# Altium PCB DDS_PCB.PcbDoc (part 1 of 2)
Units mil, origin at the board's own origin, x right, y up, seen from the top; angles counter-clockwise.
Board outline 3998.07 x 3476.44 mil, 8 copper layers (TOP_L1, Plane_L2, Inner_L3, Plane_L4, Plane_L5, Inner_L6, Plane_L7, Bottom Layer_L8), stack 26.8 mil thick; 448 components, 266 nets, 1489 pads, 18 vias.
Unrouted connection lines stored in the file: 995.
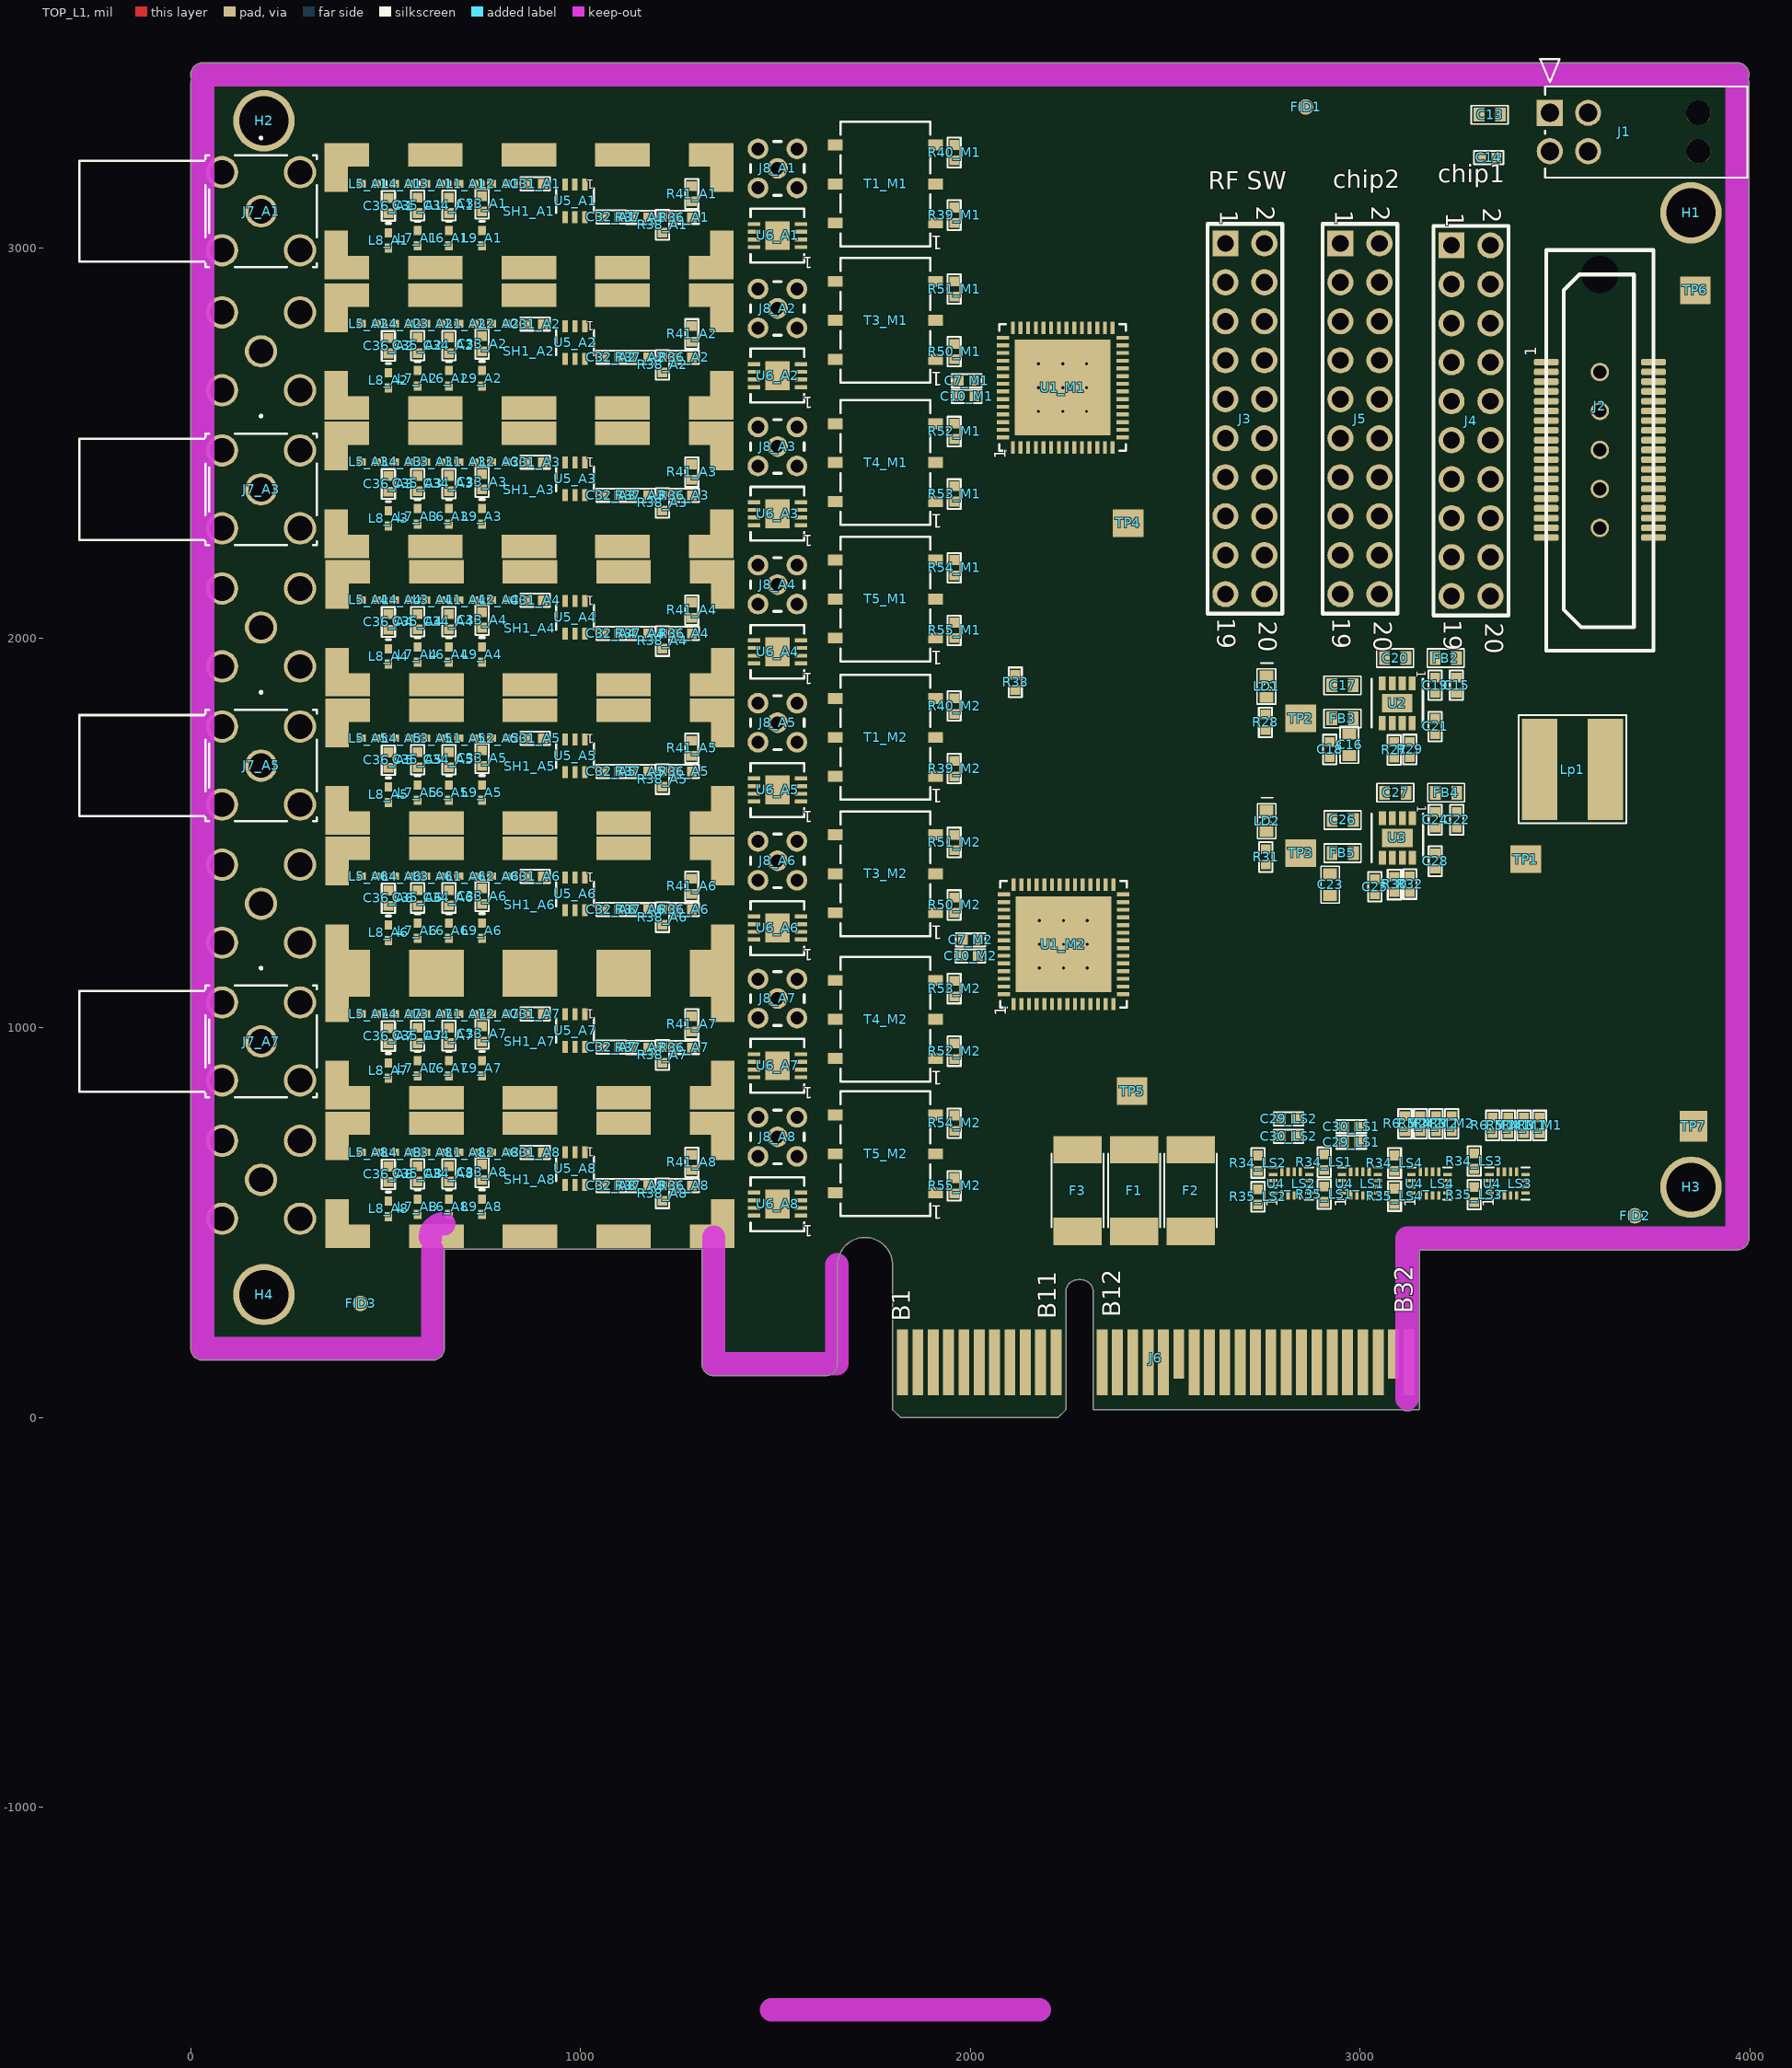
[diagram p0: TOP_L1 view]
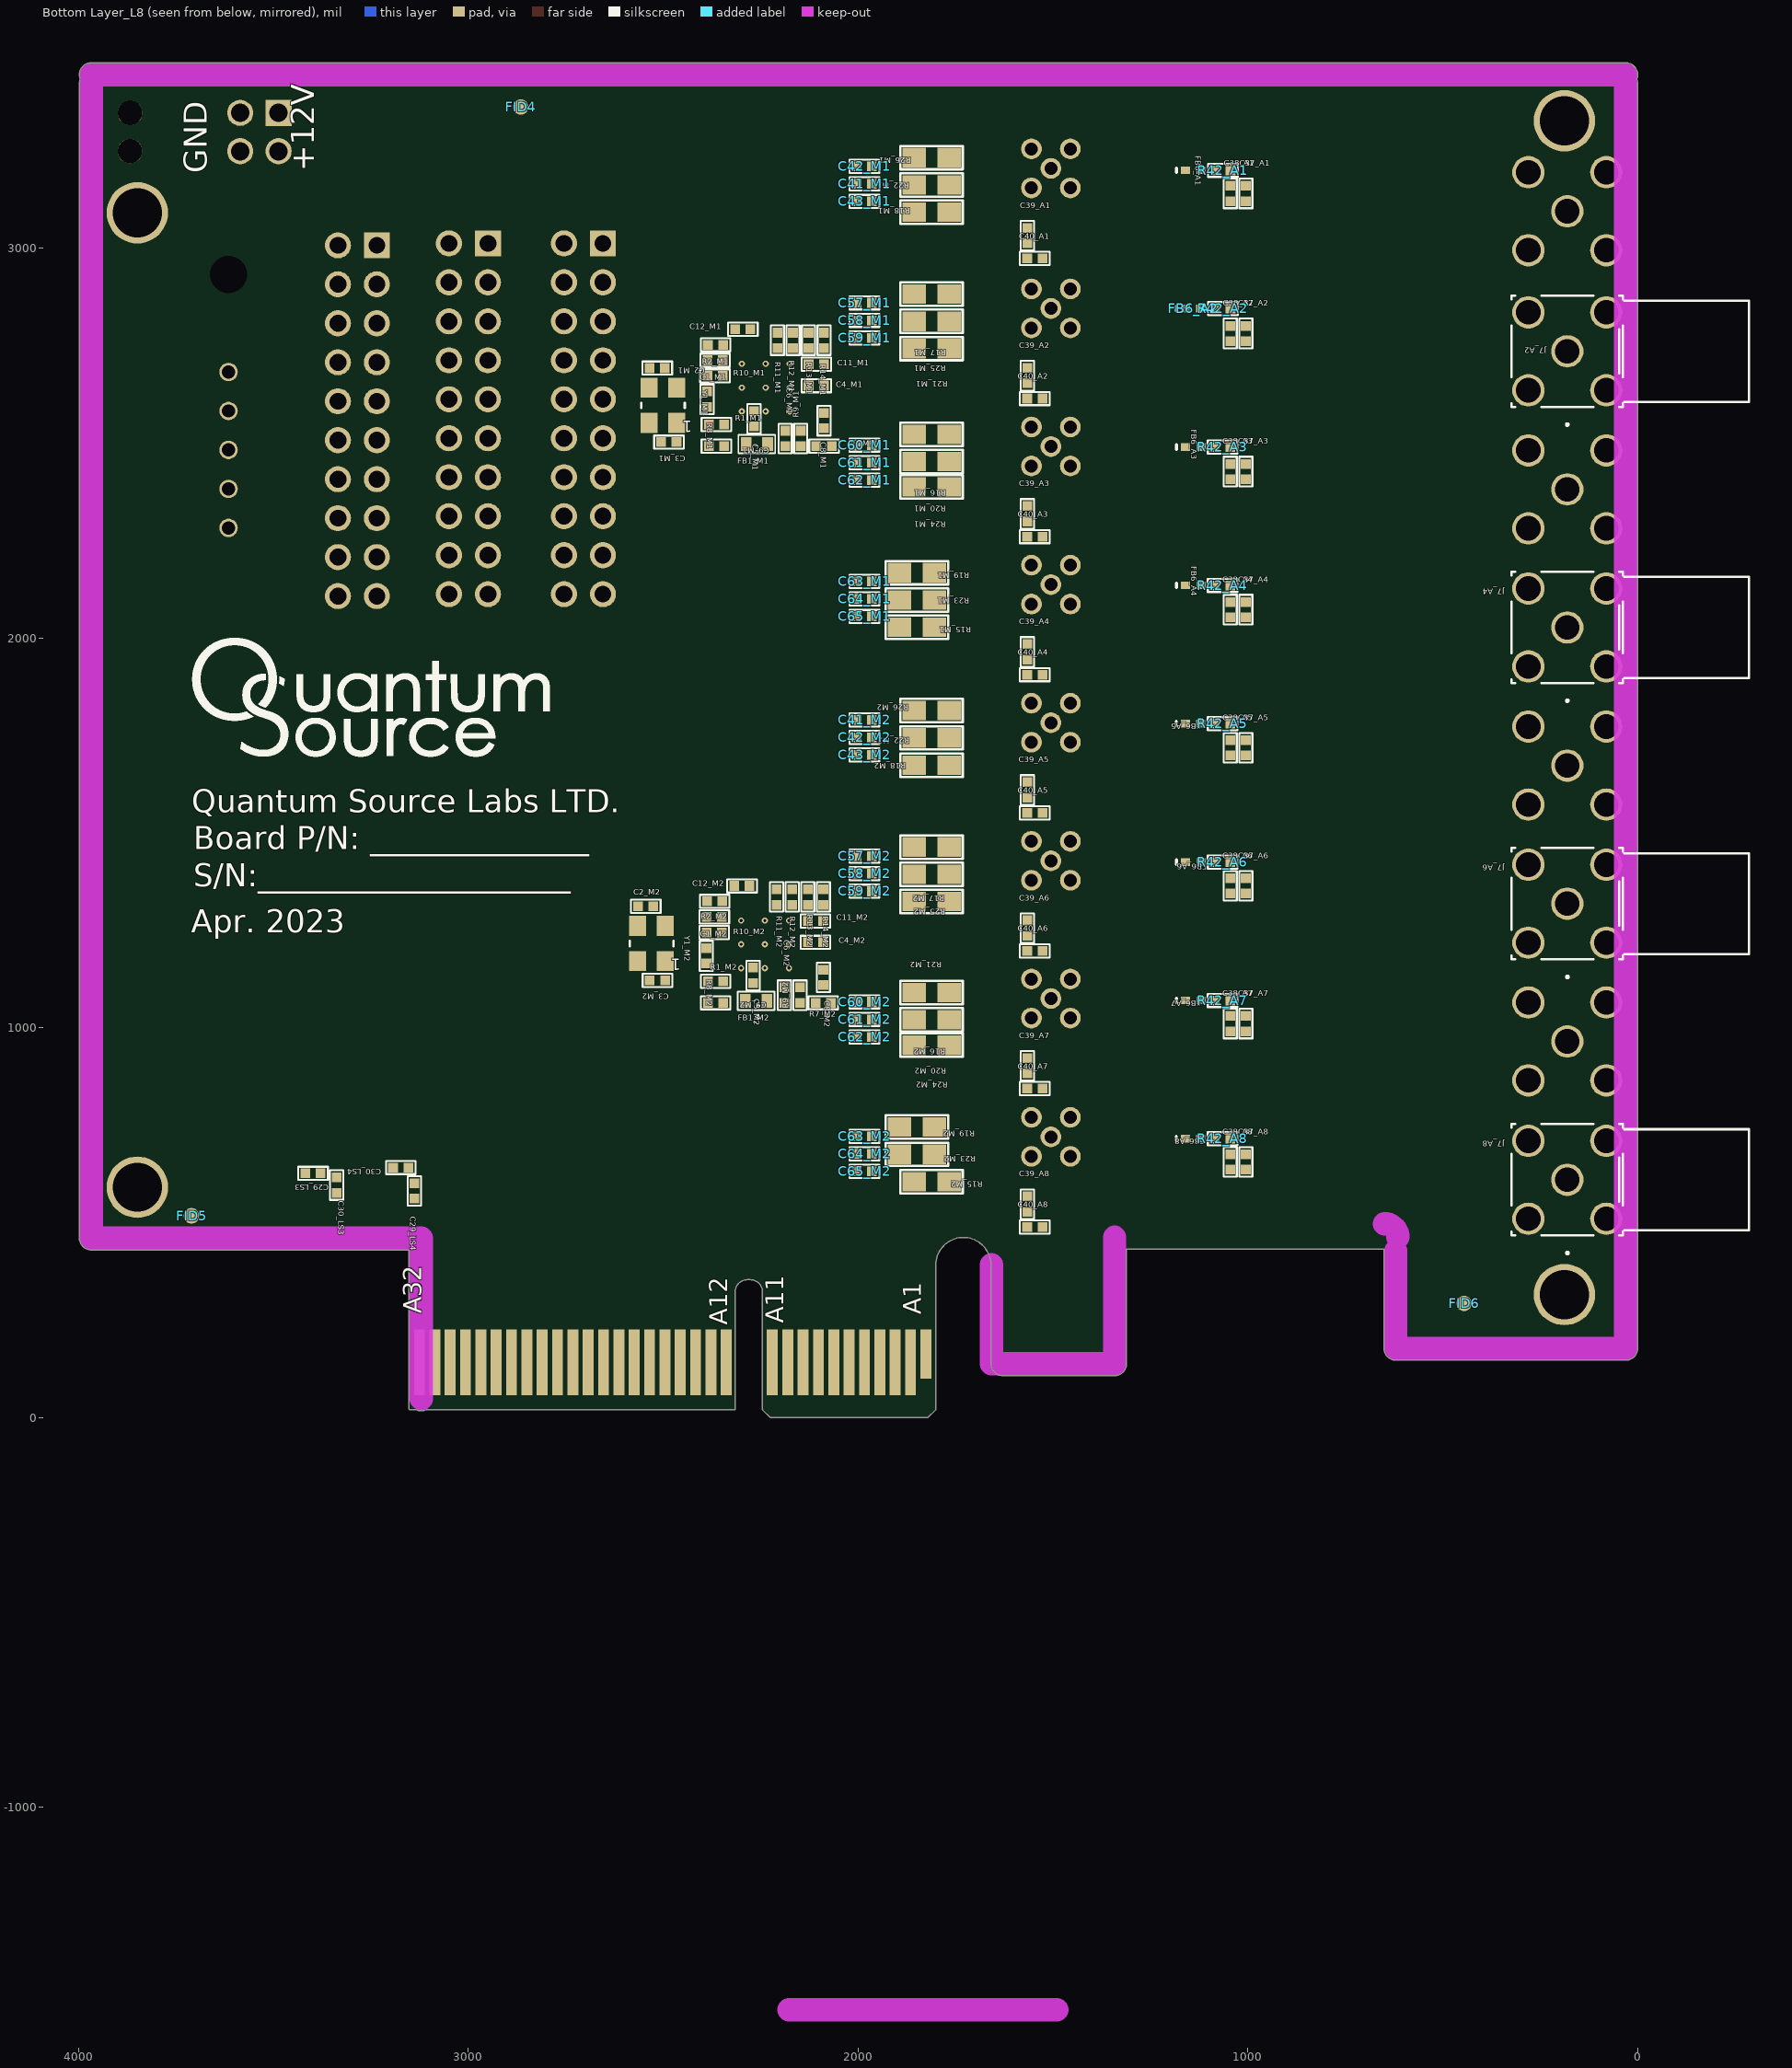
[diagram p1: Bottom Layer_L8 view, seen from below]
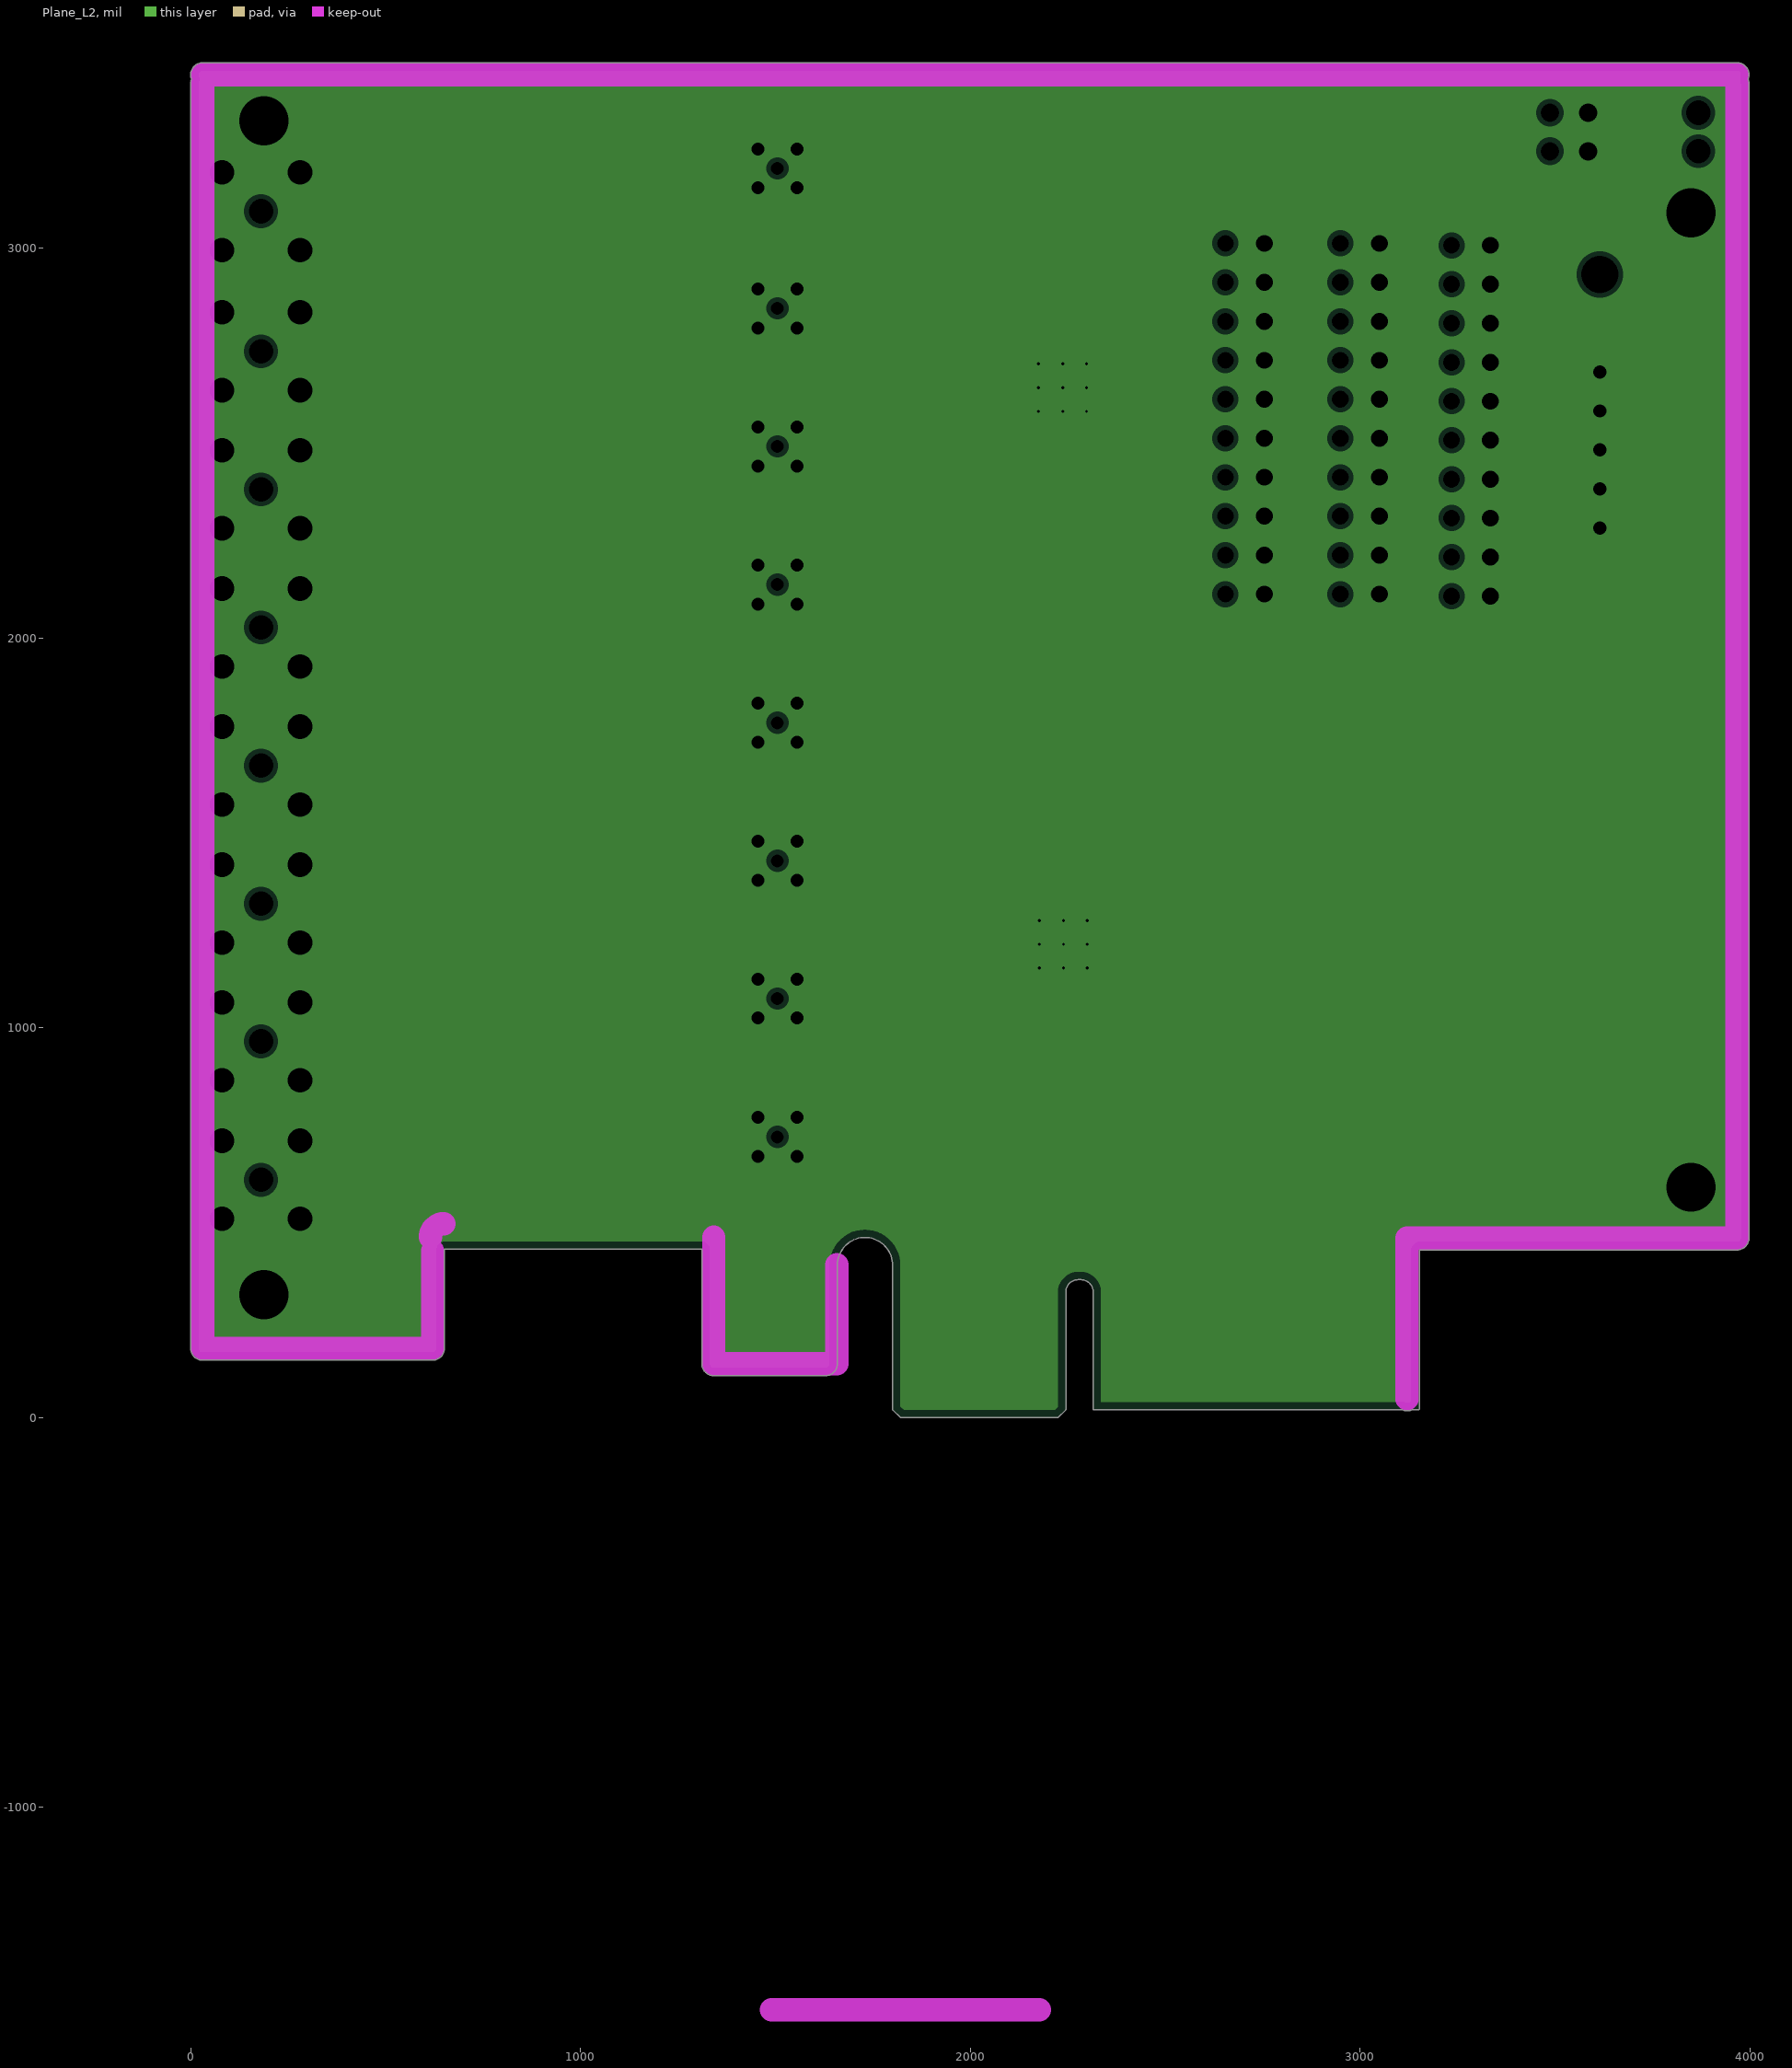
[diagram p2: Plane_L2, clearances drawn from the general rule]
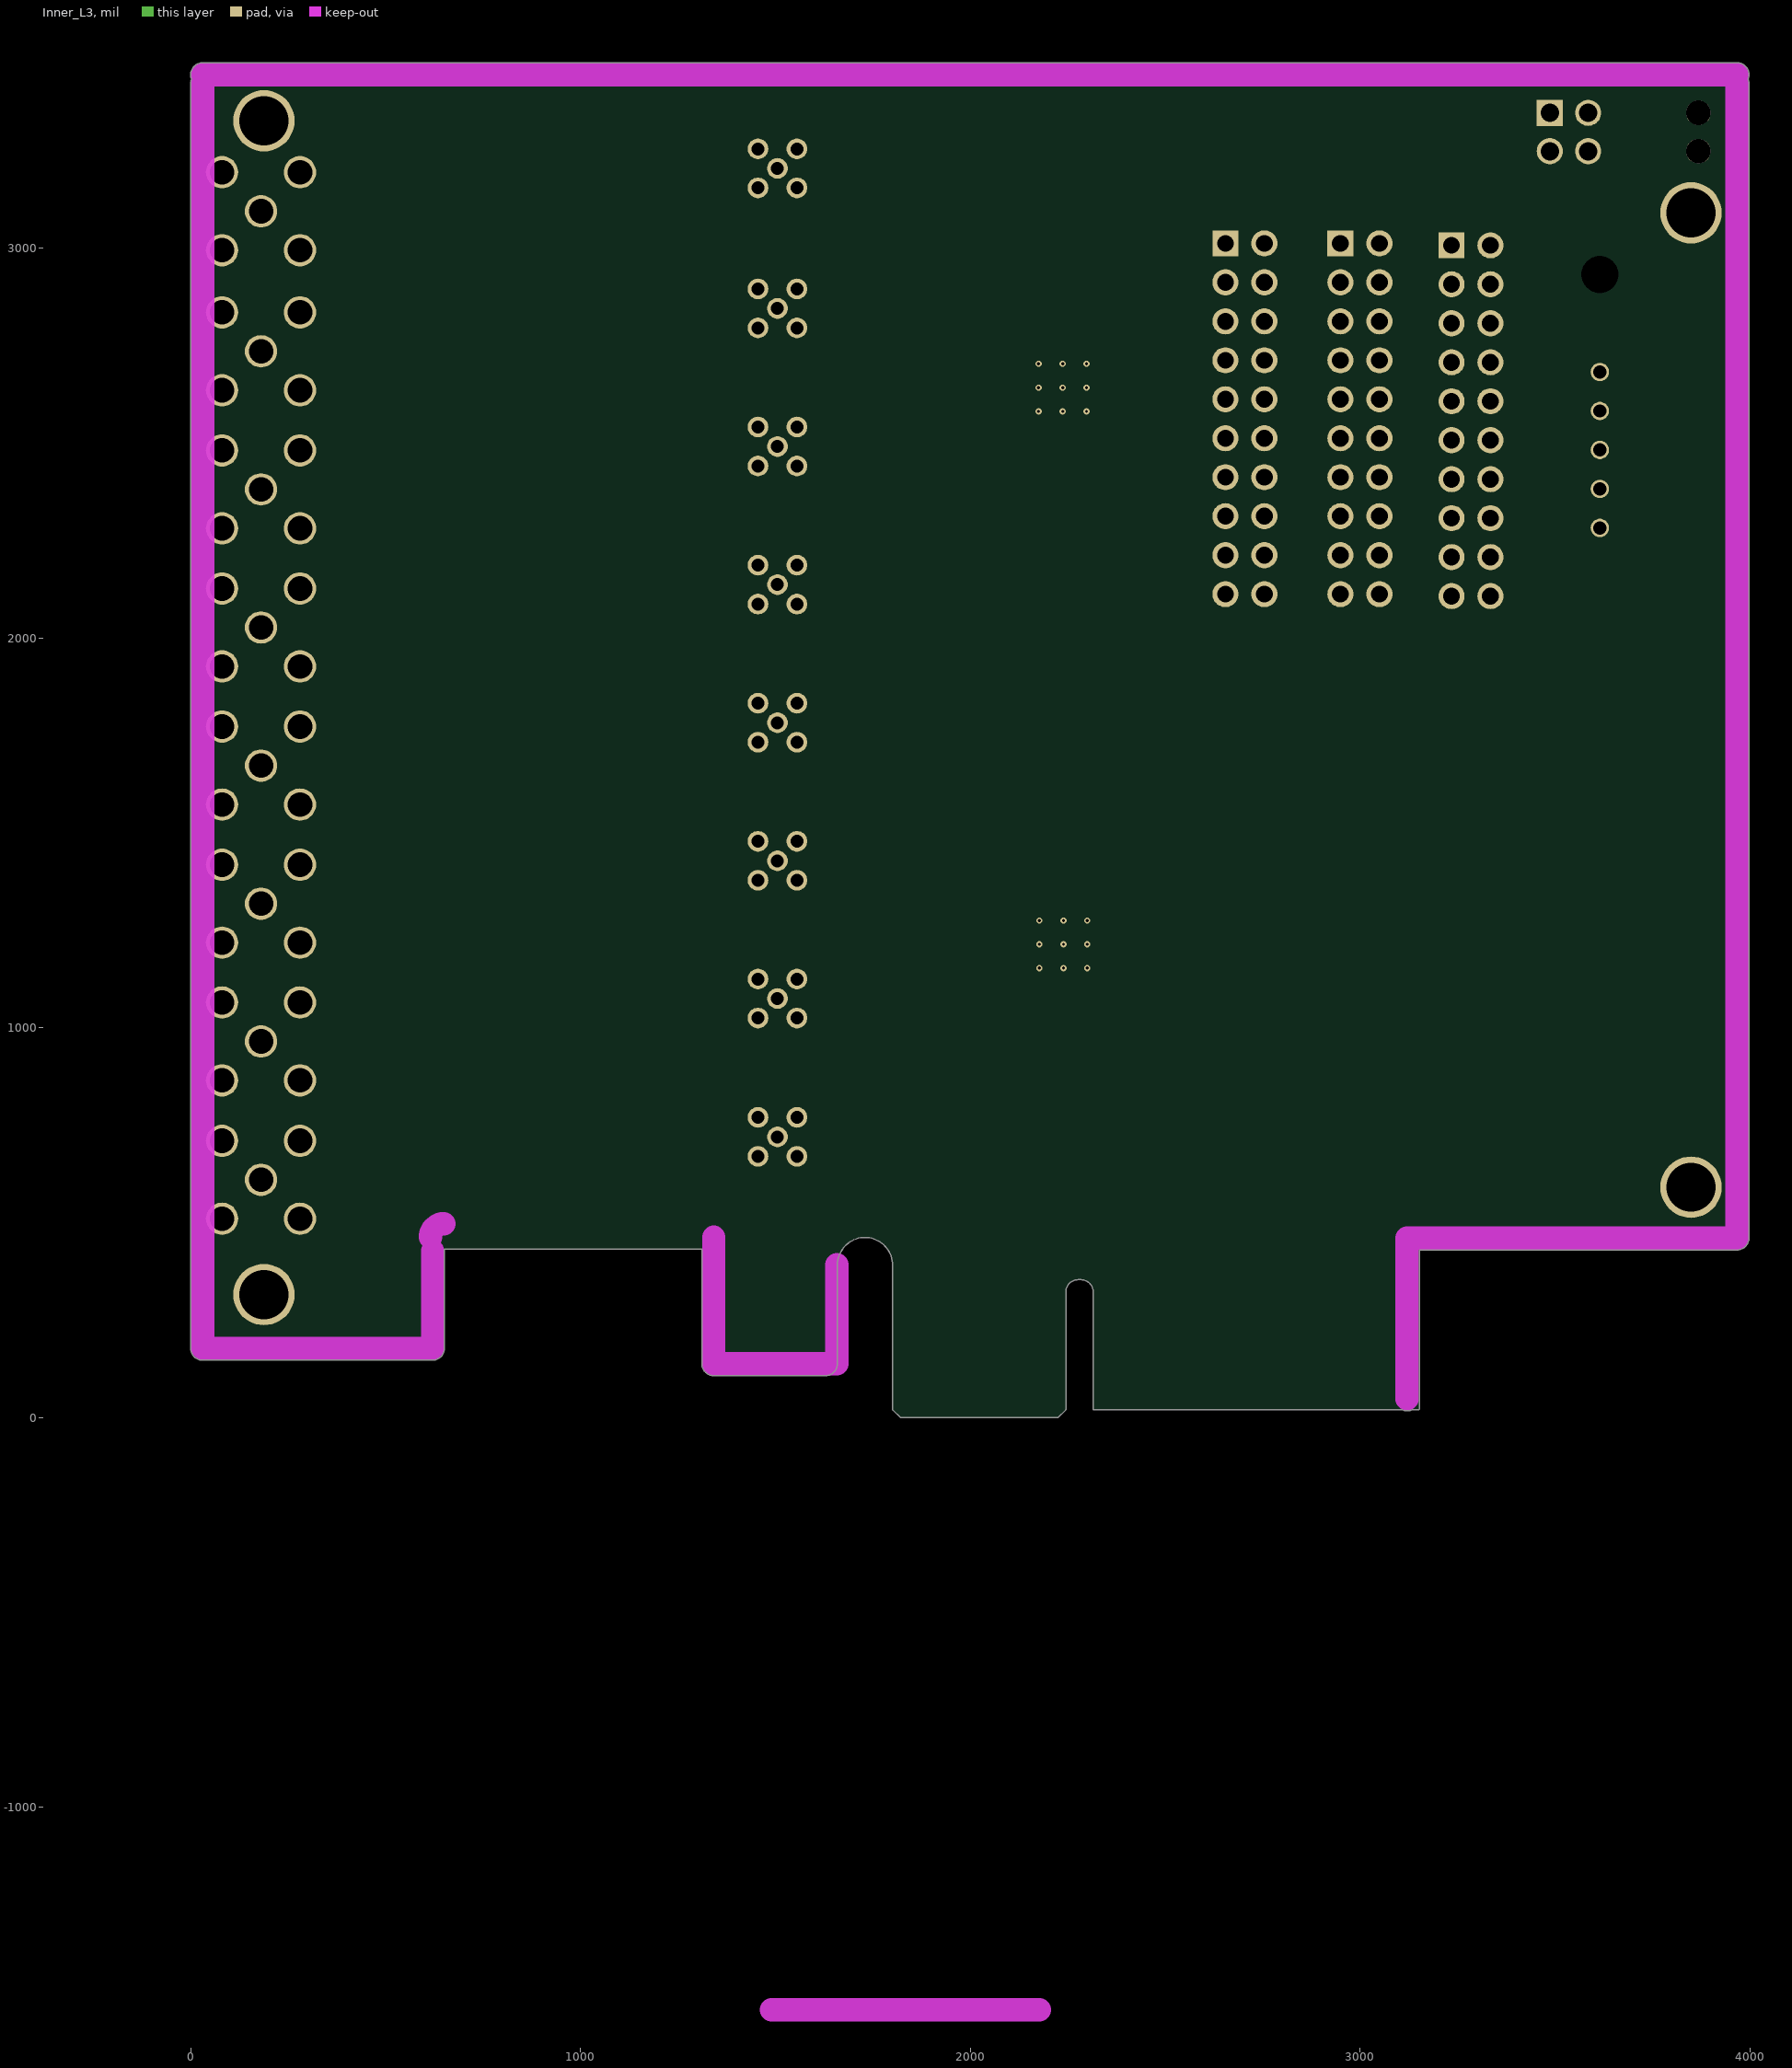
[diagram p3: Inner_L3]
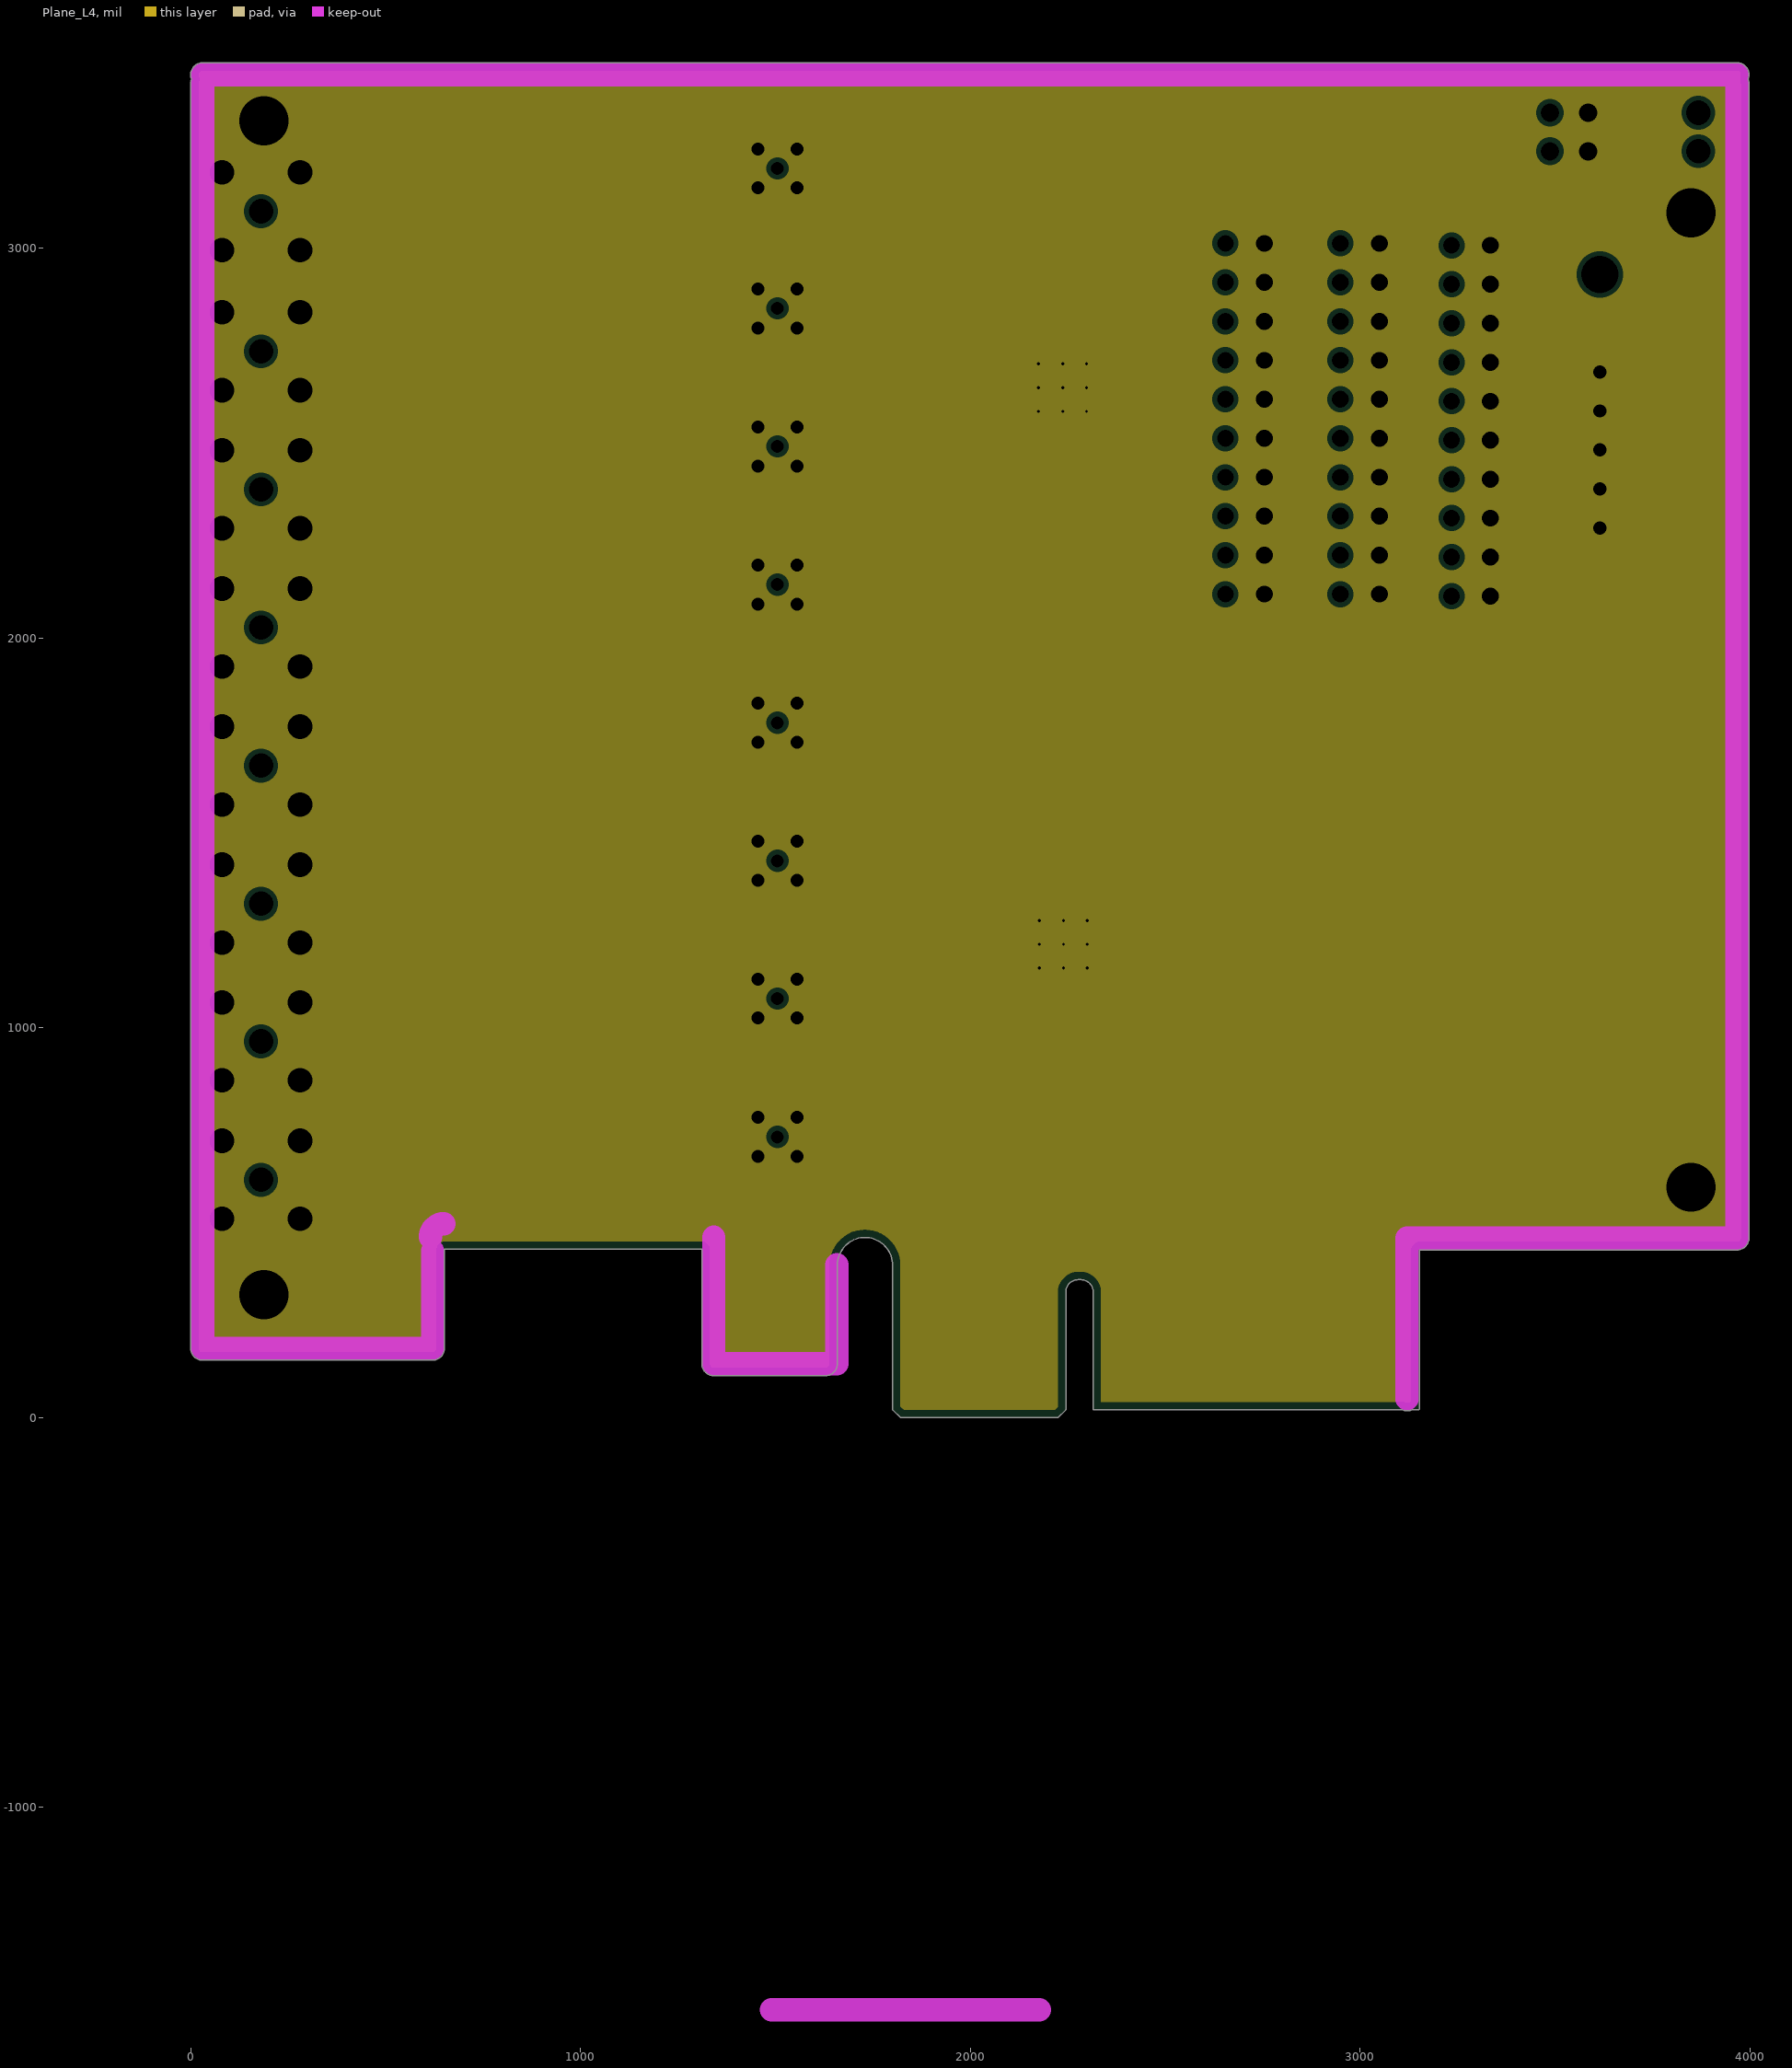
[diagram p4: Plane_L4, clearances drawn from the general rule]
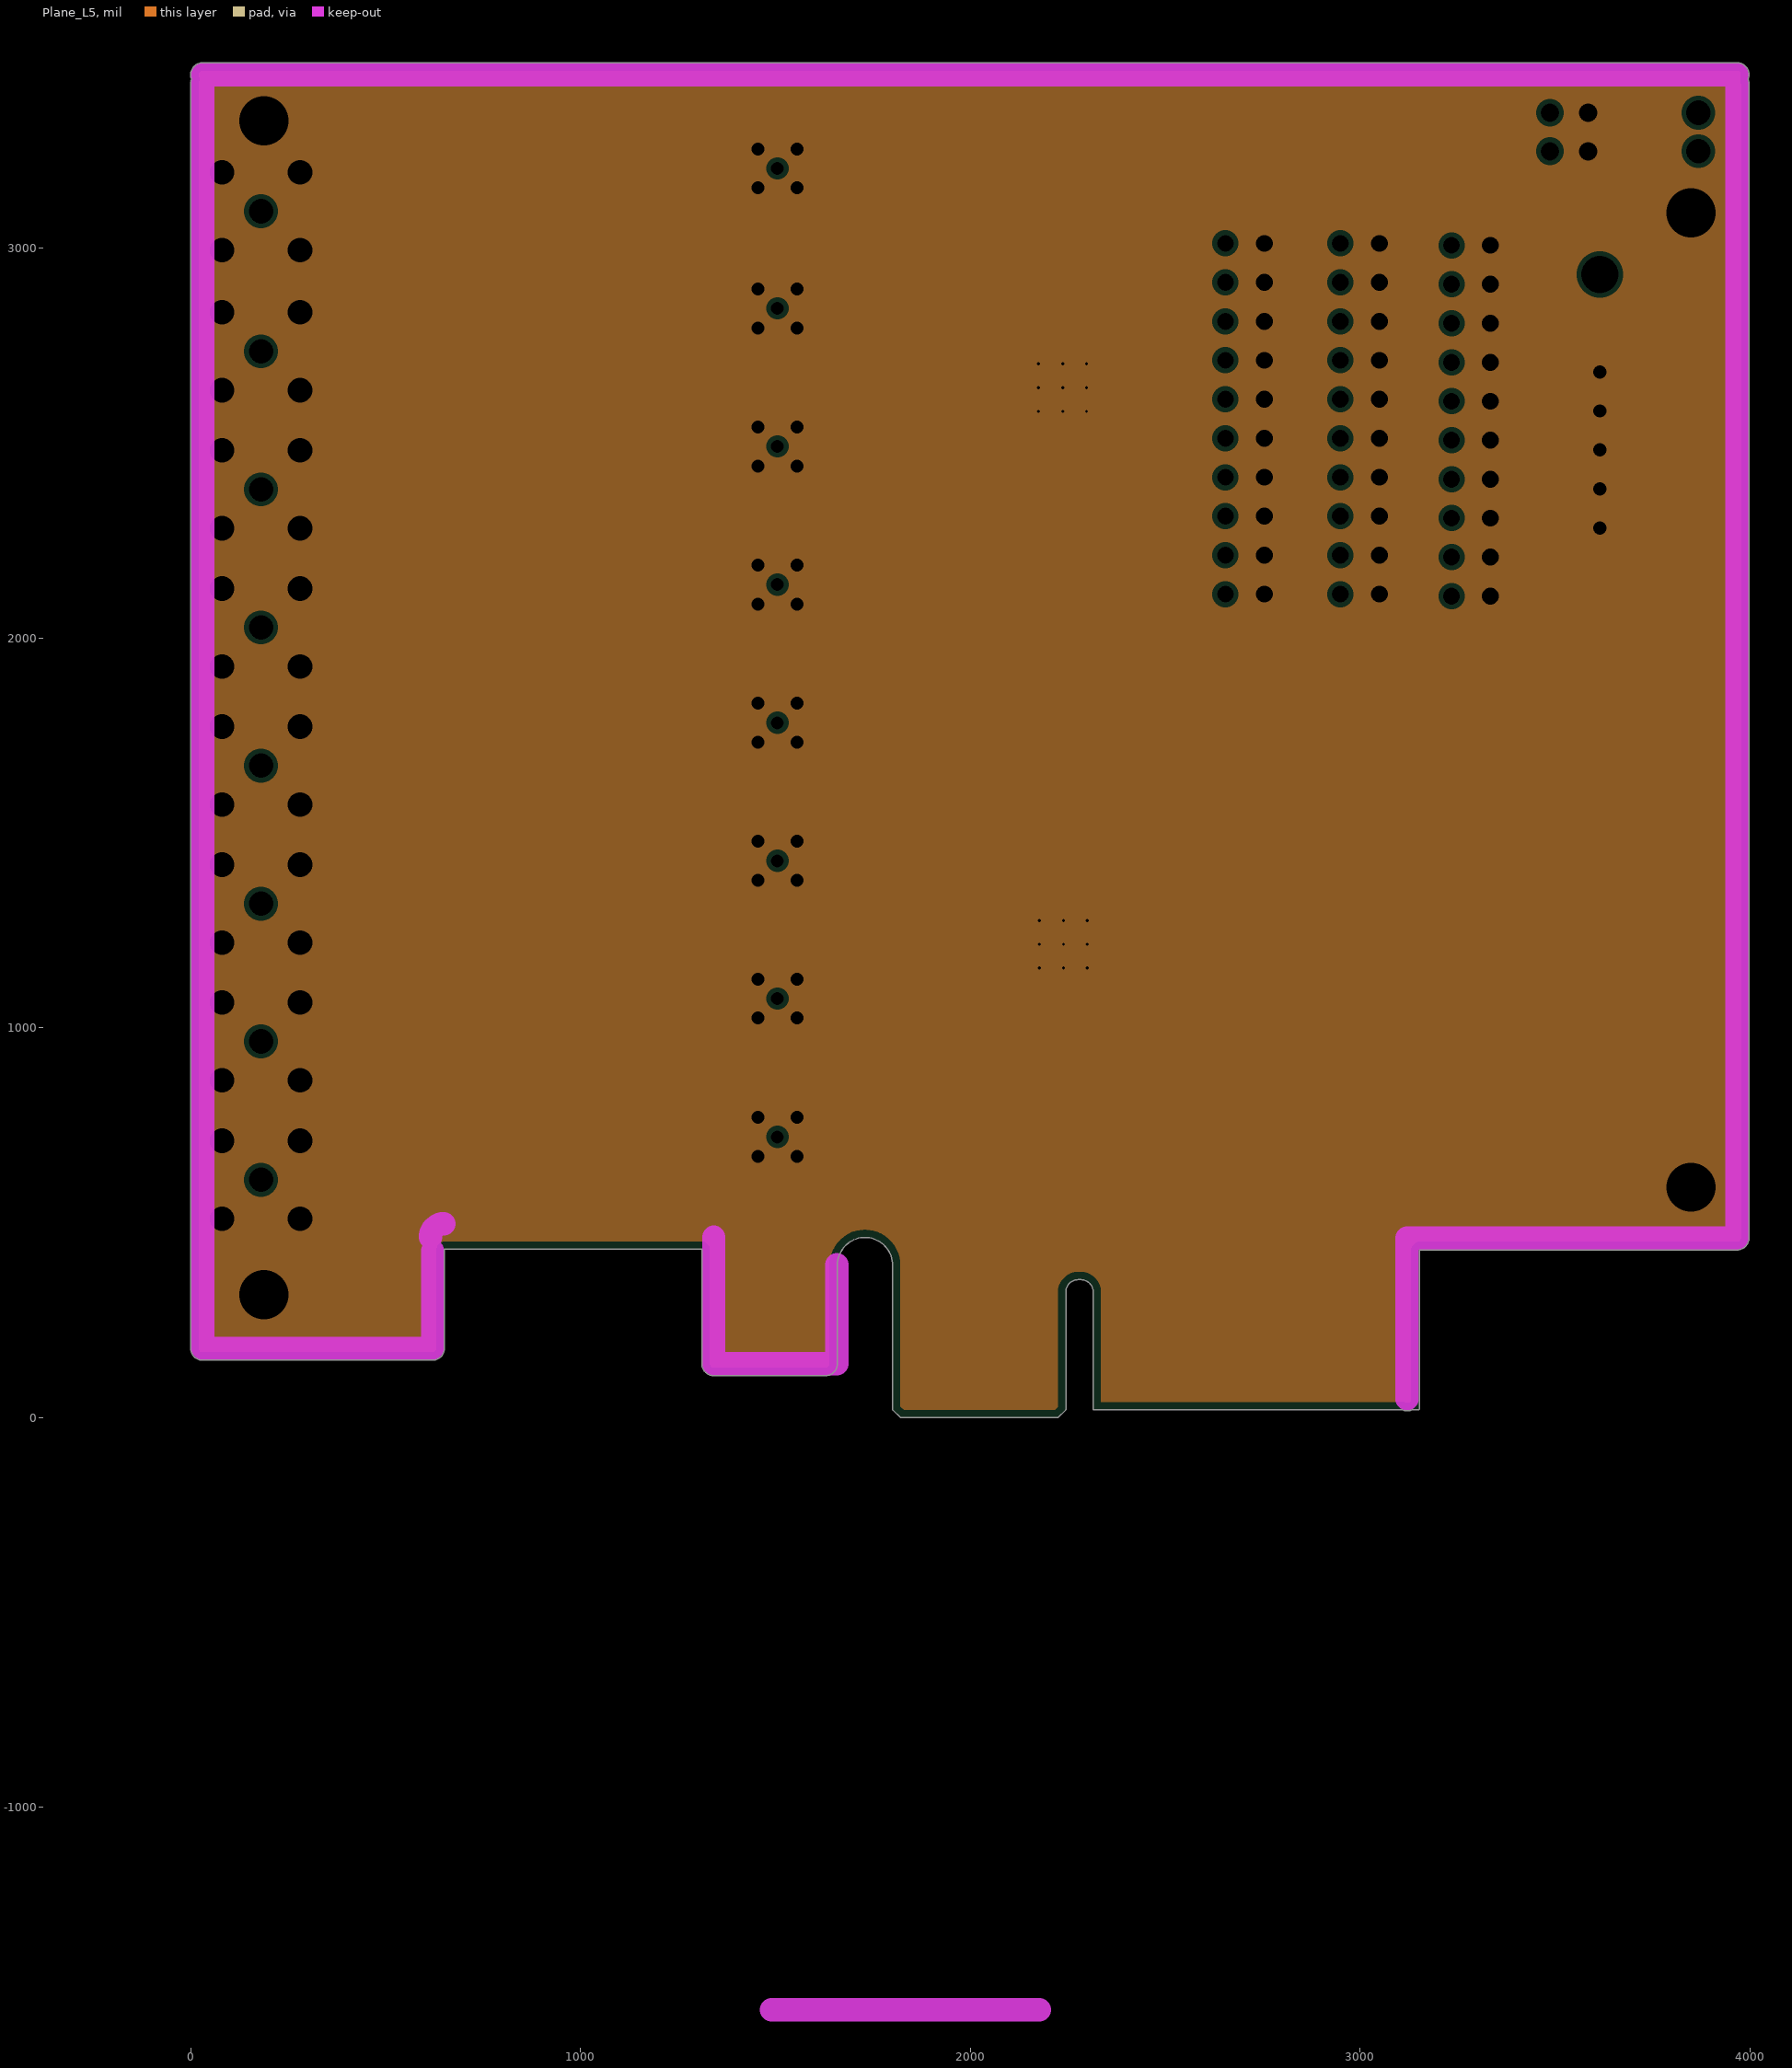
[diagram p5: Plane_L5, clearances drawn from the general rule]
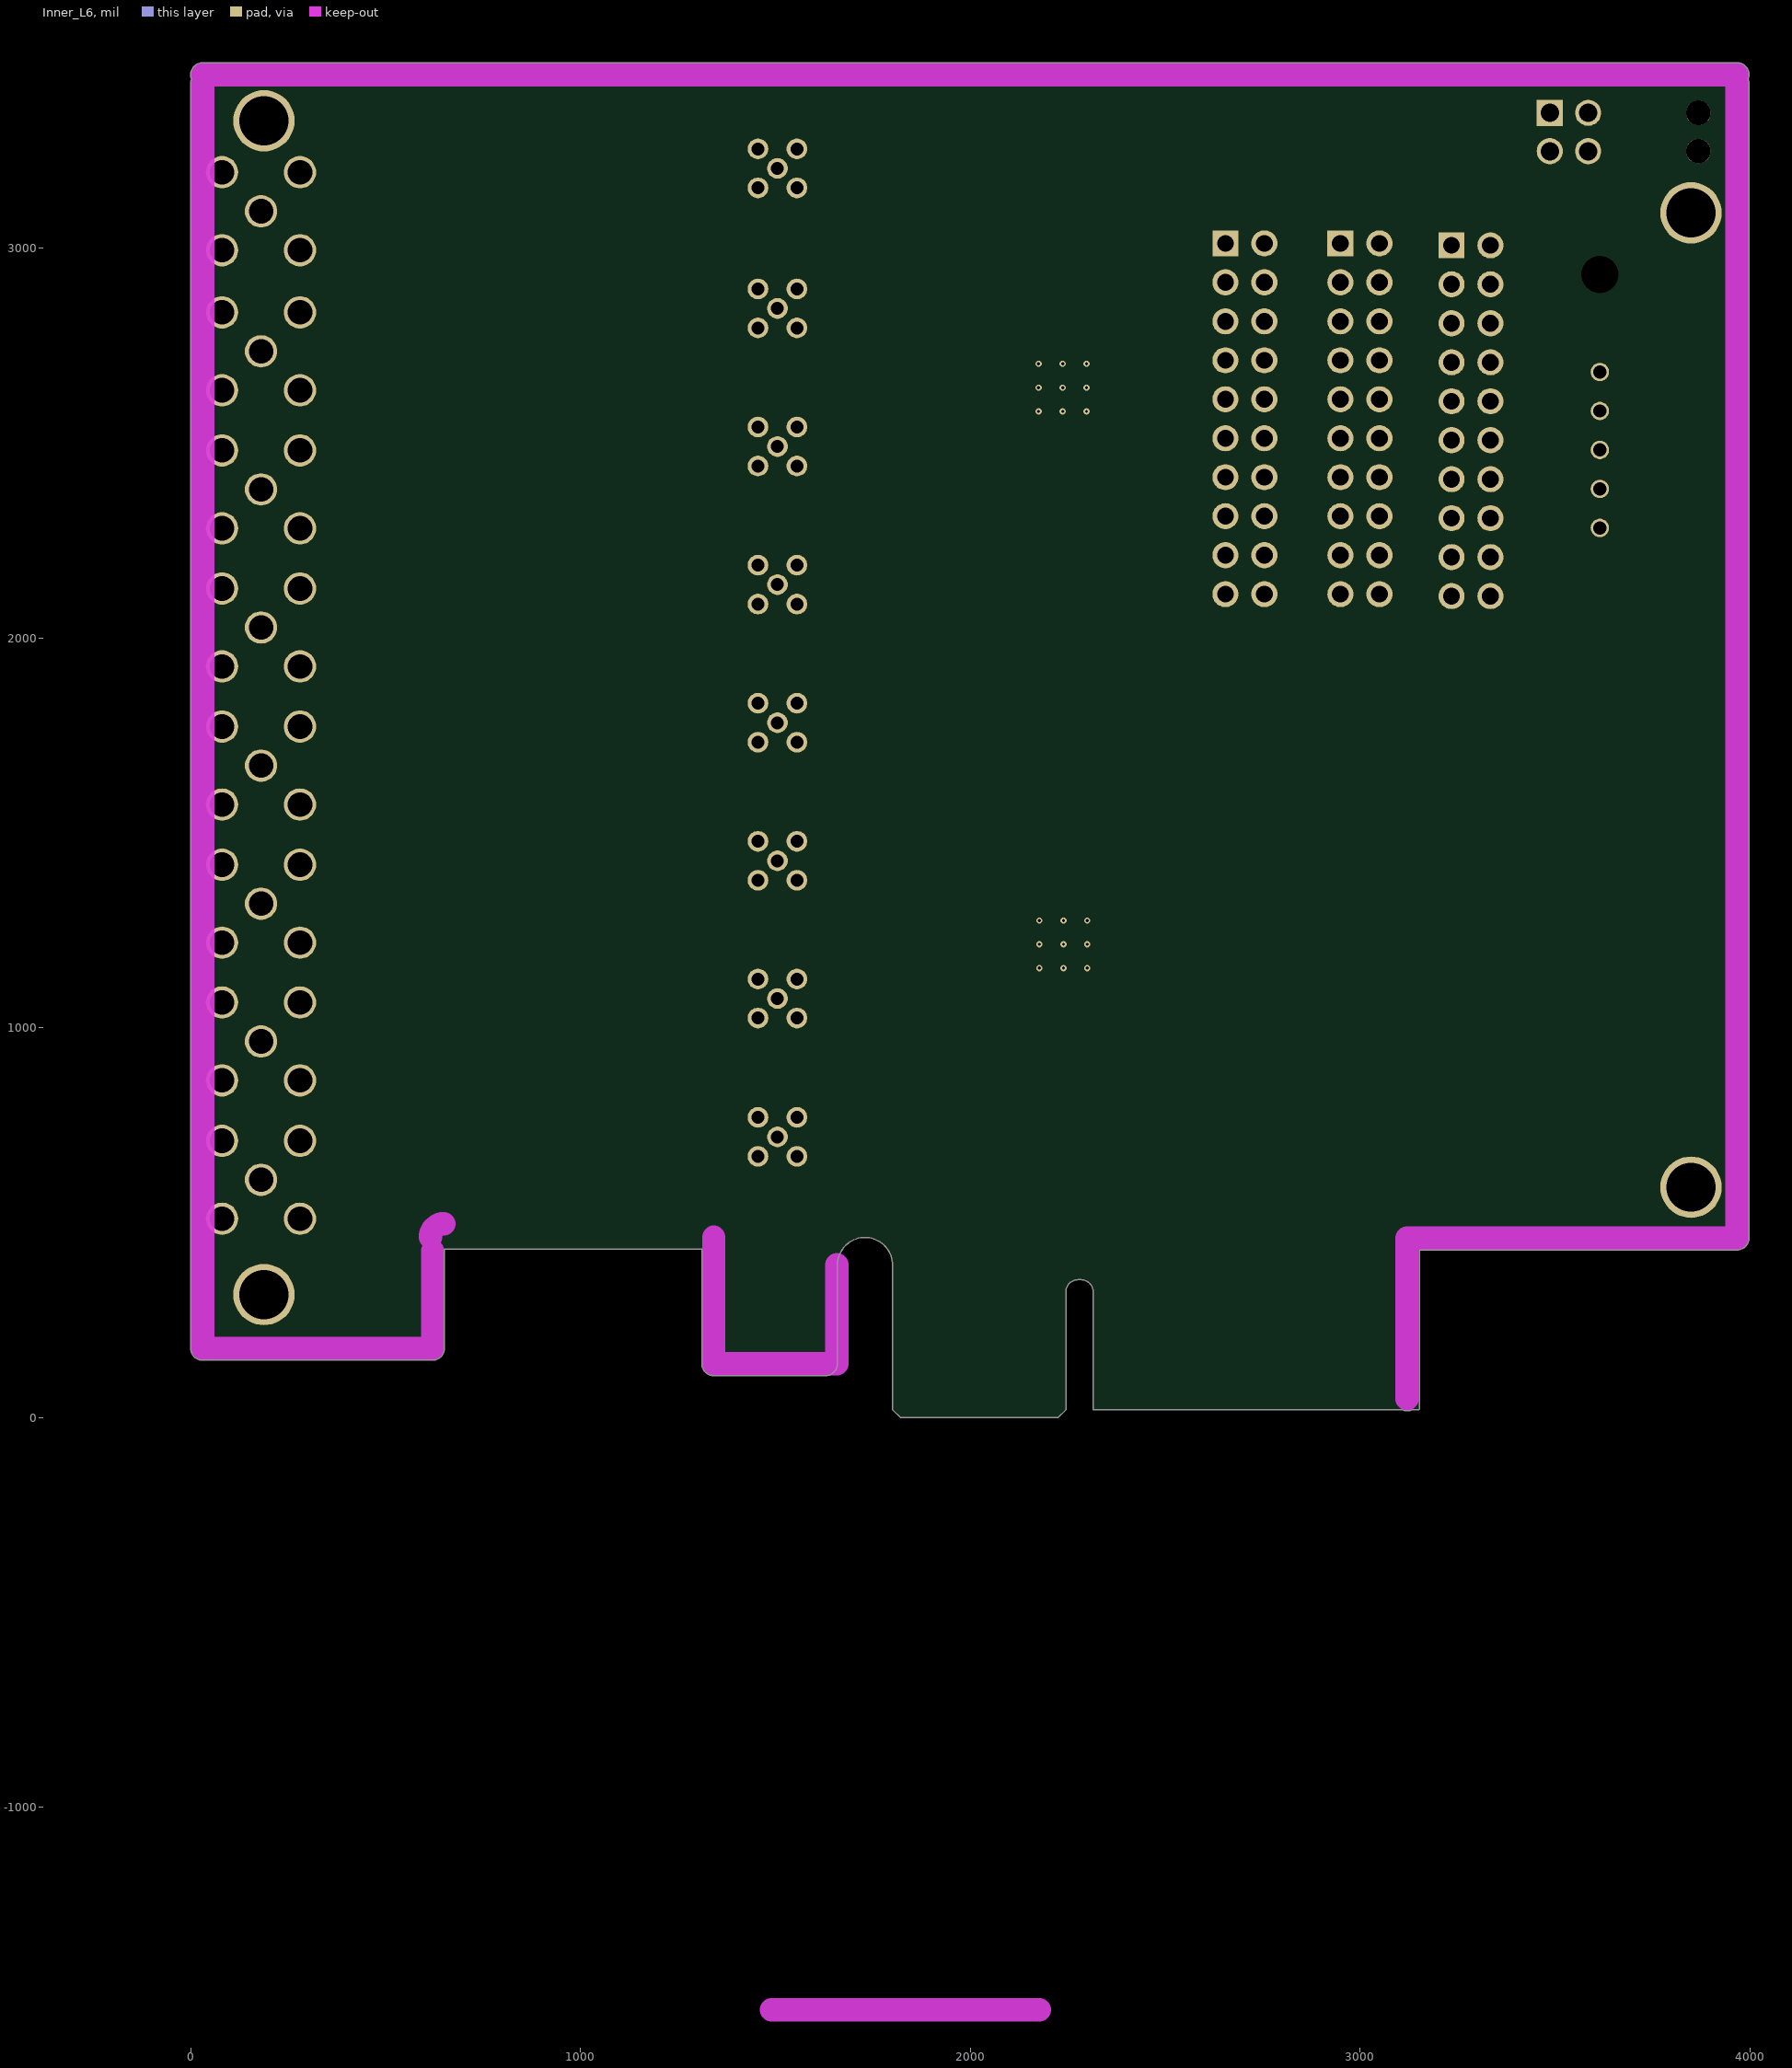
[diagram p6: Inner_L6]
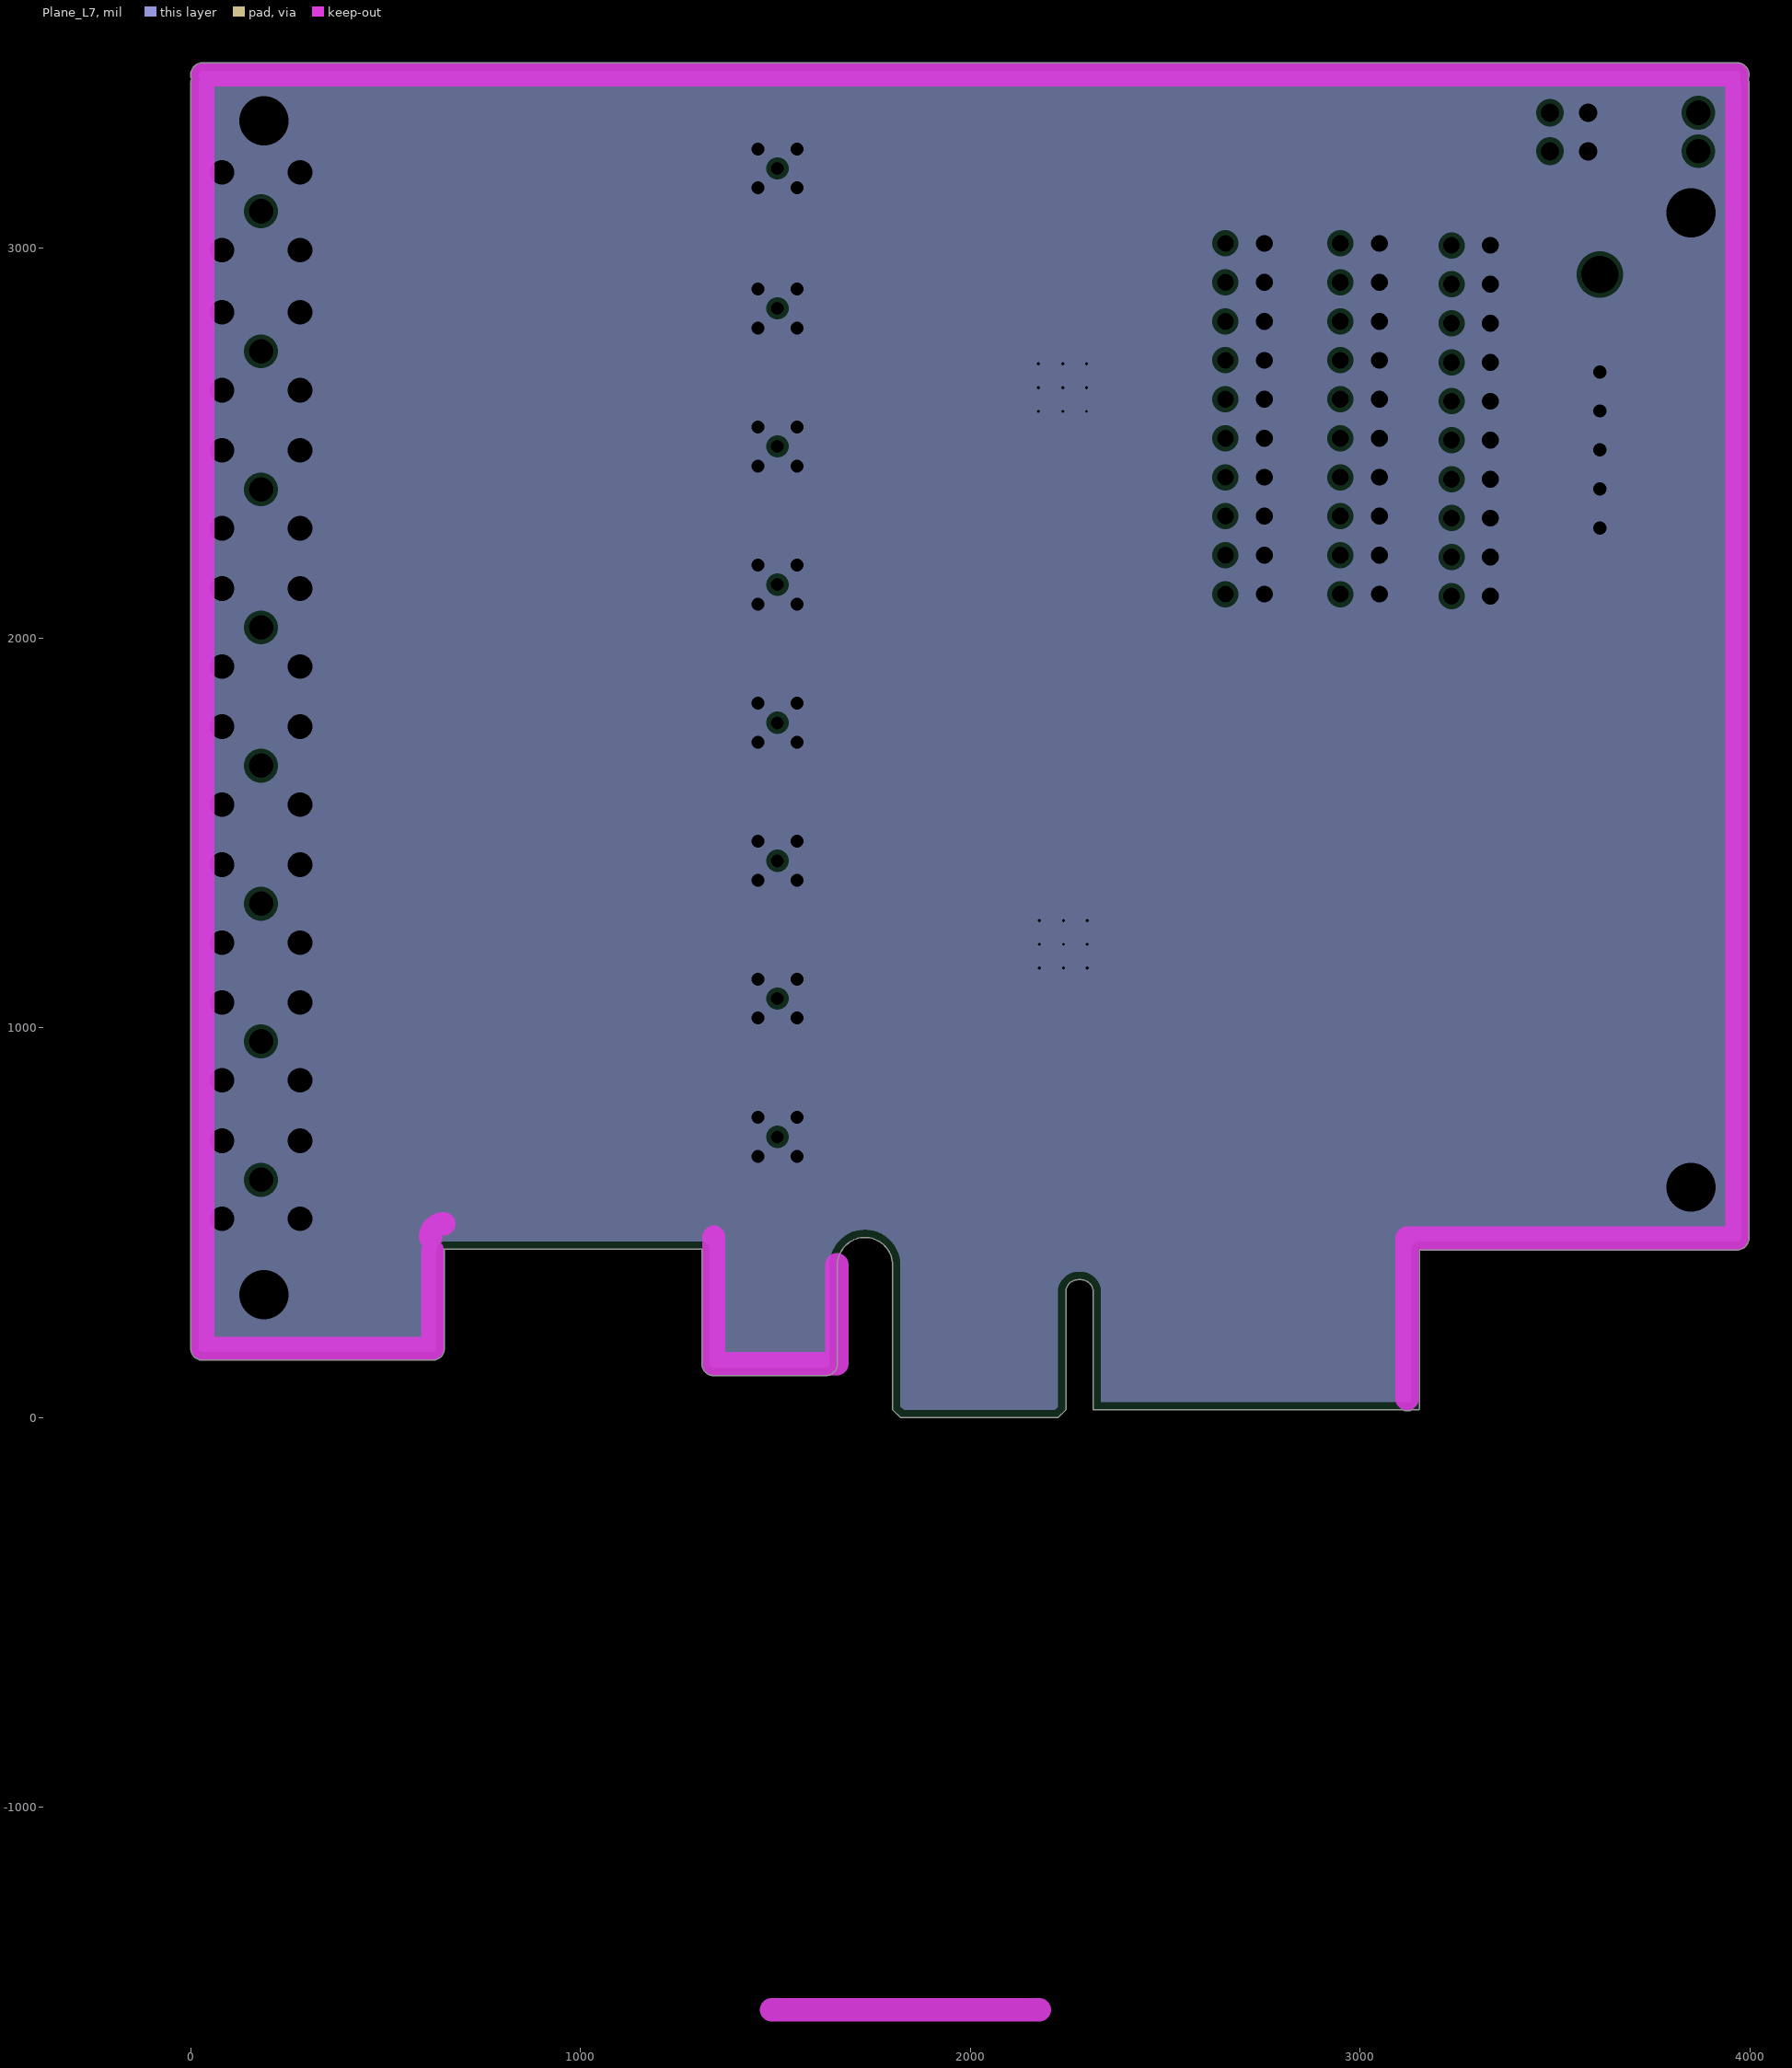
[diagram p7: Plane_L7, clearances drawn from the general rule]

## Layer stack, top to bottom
Top Solder: solder mask 0.4, Solder Resist, Dk 3.5
TOP_L1: signal copper 0.6
Dielectric1: core 2.9, FR-4, Dk 3.2
Plane_L2: plane copper 0.7, net GND
Dielectric7: prepreg 3, FR-4, Dk 3.3
Inner_L3: signal copper 0.7
Dielectric4: core 2.8, FR-4, Dk 3.1
Plane_L4: plane copper 1.2, net GND
Dielectric10: prepreg 3, FR-4, Dk 3.3
Plane_L5: plane copper 1.2, net GND
Dielectric 1: core 2.8, FR-4, Dk 3.1
Inner_L6: signal copper 0.7
Dielectric 6: prepreg 3, FR-4, Dk 3.3
Plane_L7: plane copper 0.7, net GND
Dielectric 7: core 2.9, FR-4, Dk 3.2
Bottom Layer_L8: signal copper 0.6
Board Layer Stack Bottom Solder: solder mask 0.4, Solder Resist, Dk 3.5

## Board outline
30.02,147 cw(c30.02,177.53) -0.51,177.53 -0.51,3422.53 cw(c30.02,3422.53) 1.68,3433.89 cw(c30.02,3445.25) 30.01,3475.78 30.02,3475.78 3967.02,3475.78 cw(c3967.02,3445.25) 3997.55,3445.25 3997.55,3445.24 cw(c3967.02,3445.25) 3995.36,3433.89 cw(c3967.02,3422.53) 3997.55,3422.54 3997.55,3422.53 3997.55,460.41 cw(c3967.02,460.4) 3967.02,429.87 3151.68,429.87 3151.68,20.57 3150.65,19.54 3132.64,19.54 cw(c3120.65,47.61) 3108.65,19.54 2316,19.54 2314.97,20.57 2314.97,322.33 ccw(c2283.83,322.33) 2283.83,353.47 2276.2,353.47 ccw(c2276.2,322.18) 2244.91,322.18 2244.91,20.2 2244.61,19.47 2224.78,-0.36 2224.05,-0.66 1821.35,-0.66 1820.63,-0.36 1800.68,19.38 1800.12,20.35 1800.12,391.24 ccw(c1729.4,391.24) 1729.4,461.96 1729.39,461.96 ccw(c1729.39,392.09) 1665.72,420.87 1665.05,420.6 ccw(c1729.39,391.24) 1658.66,391.24 1658.66,138.36 1658.67,138.28 cw(c1627.63,138.28) 1627.63,107.24 1342.01,107.24 cw(c1342.01,138.28) 1310.96,138.28 1310.96,432.04 650.61,432.04 650.61,178.05 cw(c619.57,178.05) 619.57,147

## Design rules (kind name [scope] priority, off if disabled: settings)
Clearance [All] p1: gap=8 ignorepadtopadclearanceinfootprint=FALSE except(0: Arc-Hole Track-Hole SMDPad-Hole THPad-Hole Via-Hole Fill-Hole Poly-Hole Region-Hole Text-Hole)
DiffPairsRouting DiffPair_100OhmDiffPairsRouting [InDifferentialPairClass('New Class_100Ohm')] p1: maxlimit=6.5 minlimit=6 mostfreqgap=6.5 toplayer_maxgap=6 toplayer_prefgap=6 toplayer_minwidth=15 toplayer_maxwidth=15 toplayer_prefwidth=15 midlayer2_mingap=6.5 midlayer2_minwidth=15 midlayer2_maxwidth=15 midlayer2_prefwidth=15 midlayer4_mingap=6.5 midlayer4_minwidth=15 midlayer4_maxwidth=15 midlayer4_prefwidth=15 bottomlayer_maxgap=6 bottomlayer_prefgap=6 bottomlayer_minwidth=15 bottomlayer_maxwidth=15 bottomlayer_prefwidth=15 maxuncoupledlength=500
Length Length_GPIO2_[0..15] [InNetClass('GPIO2_[0..15]')] p1: maxlimit=1628 minlimit=1600
Length Length_DDR3_A0-15_control [InNetClass('DDR3_A[0..15]_CONTROL')] p2: maxlimit=2401 minlimit=2400
Length Length_SSF_TD1-6 [InDifferentialPairClass('New Class_SSF_TD1-6')] p3: maxlimit=10579 minlimit=10578
Length Length_PCI_RX0-7 [InDifferentialPairClass('New Class_PCI_RX0-6')] p4: maxlimit=2601 minlimit=2600
Length Length_PCI_TX0-7 [InDifferentialPairClass('New Class_PCI_TX0-6')] p5: maxlimit=2016 minlimit=2015
MatchedLengths DiffPair_85OhmMatchedLengths [All] p1: tolerance=25 checknetsindiffpair=TRUE checkdiffpairvsdiffpair=FALSE checkxsignals=FALSE checkothers=FALSE
MatchedLengths DiffPair_80OhmMatchedLengths [All] p2: tolerance=25 checknetsindiffpair=TRUE checkdiffpairvsdiffpair=FALSE checkxsignals=FALSE checkothers=FALSE
MatchedLengths DiffPair_100OhmMatchedLengths [All] p3: tolerance=25 checknetsindiffpair=TRUE checkdiffpairvsdiffpair=FALSE checkxsignals=FALSE checkothers=FALSE
PlaneClearance [All] p1: clearance=12
PlaneConnect PlaneConnect_Via [Isvia] p1: planeconnectstyle=Direct reliefexpansion=20 reliefentries=4 reliefconductorwidth=10 reliefairgap=10
PlaneConnect [All] p2: planeconnectstyle=Relief reliefexpansion=20 reliefentries=4 reliefconductorwidth=20 reliefairgap=8
PolygonConnect PolygonConnect_Via [Isvia] p1: connectstyle=Direct reliefconductorwidth=10 reliefentries=4 polygonreliefangle="90 Angle" airgapwidth=10
PolygonConnect PolygonConnect_TPs [InComponentClass('New Class_TPs')] p2: connectstyle=Direct reliefconductorwidth=10 reliefentries=4 polygonreliefangle="90 Angle" airgapwidth=10
PolygonConnect [All] p3: connectstyle=Relief reliefconductorwidth=20 reliefentries=4 polygonreliefangle="90 Angle" airgapwidth=10
RoomDefinition A2 [InComponentClass('A2')] p1: confinementstyle=ConfineIn formatcopy=TRUE lockcomponents=FALSE outline -299.98,2548.72 1610.02,2548.72 1610.02,2953.72 -299.98,2953.72
RoomDefinition A6 [InComponentClass('A6')] p2: confinementstyle=ConfineIn formatcopy=TRUE lockcomponents=FALSE outline -299.98,1131.39 1610.02,1131.39 1610.02,1536.39 -299.98,1536.39
RoomDefinition A7 [InComponentClass('A7')] p3: confinementstyle=ConfineIn formatcopy=TRUE lockcomponents=FALSE outline -299.98,778.05 1610.02,778.05 1610.02,1183.05 -299.98,1183.05
RoomDefinition A1 [InComponentClass('A1')] p4: confinementstyle=ConfineIn formatcopy=TRUE lockcomponents=FALSE outline -304.98,2888.05 1610.02,2888.05 1610.02,3313.05 -304.98,3313.05
RoomDefinition A8 [InComponentClass('A8')] p5: confinementstyle=ConfineIn formatcopy=TRUE lockcomponents=FALSE outline -299.98,423.05 1610.02,423.05 1610.02,828.05 -299.98,828.05
RoomDefinition A5 [InComponentClass('A5')] p6: confinementstyle=ConfineIn formatcopy=TRUE lockcomponents=FALSE outline -299.98,1485.72 1610.02,1485.72 1610.02,1890.72 -299.98,1890.72
RoomDefinition A4 [InComponentClass('A4')] p7: confinementstyle=ConfineIn formatcopy=TRUE lockcomponents=FALSE outline -299.98,1840.06 1610.02,1840.06 1610.02,2245.06 -299.98,2245.06
RoomDefinition A3 [InComponentClass('A3')] p8: confinementstyle=ConfineIn formatcopy=TRUE lockcomponents=FALSE outline -299.98,2194.39 1610.02,2194.39 1610.02,2599.39 -299.98,2599.39
RoutingVias [All] p1: holewidth=8 width=17 viastyle="Through Hole" minholewidth=8 minwidth=17 maxholewidth=20 maxwidth=32
SilkToSolderMaskClearance SilkscreenOverComponentPads [IsPad] p1: minsilkscreentomaskgap=10 clearancetoexposedcopper=TRUE
SolderMaskExpansion [All] p1: expansion=4 istentingtop=FALSE
Width [All] p1: maxlimit=100 minlimit=6 preferedwidth=8
26 further rules are at their usual default settings.

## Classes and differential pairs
component class A8: C31_A8 C32_A8 C33_A8 C34_A8 C35_A8 C36_A8 C37_A8 C38_A8 C39_A8 C40_A8 FB6_A8 J7_A8 J8_A8 L1_A8 L2_A8 L3_A8 L4_A8 L5_A8 L6_A8 L7_A8 L8_A8 L9_A8 R36_A8 R37_A8 R38_A8 R41_A8 R42_A8 SH1_A8 U5_A8 U6_A8
component class A7: C31_A7 C32_A7 C33_A7 C34_A7 C35_A7 C36_A7 C37_A7 C38_A7 C39_A7 C40_A7 FB6_A7 J7_A7 J8_A7 L1_A7 L2_A7 L3_A7 L4_A7 L5_A7 L6_A7 L7_A7 L8_A7 L9_A7 R36_A7 R37_A7 R38_A7 R41_A7 R42_A7 SH1_A7 U5_A7 U6_A7
component class A6: C31_A6 C32_A6 C33_A6 C34_A6 C35_A6 C36_A6 C37_A6 C38_A6 C39_A6 C40_A6 FB6_A6 J7_A6 J8_A6 L1_A6 L2_A6 L3_A6 L4_A6 L5_A6 L6_A6 L7_A6 L8_A6 L9_A6 R36_A6 R37_A6 R38_A6 R41_A6 R42_A6 SH1_A6 U5_A6 U6_A6
component class A5: C31_A5 C32_A5 C33_A5 C34_A5 C35_A5 C36_A5 C37_A5 C38_A5 C39_A5 C40_A5 FB6_A5 J7_A5 J8_A5 L1_A5 L2_A5 L3_A5 L4_A5 L5_A5 L6_A5 L7_A5 L8_A5 L9_A5 R36_A5 R37_A5 R38_A5 R41_A5 R42_A5 SH1_A5 U5_A5 U6_A5
component class A3: C31_A3 C32_A3 C33_A3 C34_A3 C35_A3 C36_A3 C37_A3 C38_A3 C39_A3 C40_A3 FB6_A3 J7_A3 J8_A3 L1_A3 L2_A3 L3_A3 L4_A3 L5_A3 L6_A3 L7_A3 L8_A3 L9_A3 R36_A3 R37_A3 R38_A3 R41_A3 R42_A3 SH1_A3 U5_A3 U6_A3
component class A4: C31_A4 C32_A4 C33_A4 C34_A4 C35_A4 C36_A4 C37_A4 C38_A4 C39_A4 C40_A4 FB6_A4 J7_A4 J8_A4 L1_A4 L2_A4 L3_A4 L4_A4 L5_A4 L6_A4 L7_A4 L8_A4 L9_A4 R36_A4 R37_A4 R38_A4 R41_A4 R42_A4 SH1_A4 U5_A4 U6_A4
component class A2: C31_A2 C32_A2 C33_A2 C34_A2 C35_A2 C36_A2 C37_A2 C38_A2 C39_A2 C40_A2 FB6_A2 J7_A2 J8_A2 L1_A2 L2_A2 L3_A2 L4_A2 L5_A2 L6_A2 L7_A2 L8_A2 L9_A2 R36_A2 R37_A2 R38_A2 R41_A2 R42_A2 SH1_A2 U5_A2 U6_A2
component class A1: C31_A1 C32_A1 C33_A1 C34_A1 C35_A1 C36_A1 C37_A1 C38_A1 C39_A1 C40_A1 FB6_A1 J7_A1 J8_A1 L1_A1 L2_A1 L3_A1 L4_A1 L5_A1 L6_A1 L7_A1 L8_A1 L9_A1 R36_A1 R37_A1 R38_A1 R41_A1 R42_A1 SH1_A1 U5_A1 U6_A1
channel class analog_channel: A1 A2 A3 A4 A5 A6 A7 A8
channel class "Level Shifter": LS1 LS2 LS3 LS4
channel class main: M1 M2
differential pair CH3_M2: +CH3_M2_P -CH3_M2_N
differential pair CH3_M1: +CH3_M1_P -CH3_M1_N
differential pair CH2_M2: +CH2_M2_P -CH2_M2_N
differential pair CH2_M1: +CH2_M1_P -CH2_M1_N
differential pair CH1_M2: +CH1_M2_P -CH1_M2_N
differential pair CH1_M1: +CH1_M1_P -CH1_M1_N
differential pair CH0_M2: +CH0_M2_P -CH0_M2_N
differential pair CH0_M1: +CH0_M1_P -CH0_M1_N

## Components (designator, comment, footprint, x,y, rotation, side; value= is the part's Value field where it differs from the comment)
C1_M1 "680pF 50V" C0402 2367.75,2712.52 r180 bottom (schematic designator C1)
C1_M2 "680pF 50V" C0402 2369.8,1284.11 r180 bottom (schematic designator C1)
C2_M1 "39pF 50V" C0402 2516.47,2692.52 r180 bottom (schematic designator C2)
C2_M2 "39pF 50V" C0402 2545.82,1311.27 r180 bottom (schematic designator C2)
C3_M1 "39pF 50V" C0402 2486.47,2502.52 r180 bottom (schematic designator C3)
C3_M2 "39pF 50V" C0402 2515.82,1121.27 r180 bottom (schematic designator C3)
C4_M1 "1uF 25V" C0402 2108.35,2647.52 r180 bottom (schematic designator C4)
C4_M2 "1uF 25V" C0402 2110.4,1219.11 r180 bottom (schematic designator C4)
C5_M1 "1uF 25V" C0402 2266.85,2564.02 r270 bottom (schematic designator C5)
C5_M2 "1uF 25V" C0402 2268.9,1135.61 r270 bottom (schematic designator C5)
C6_M1 "1uF 25V" C0402 2186.85,2513.42 r270 bottom (schematic designator C6)
C6_M2 "1uF 25V" C0402 2188.9,1085.01 r270 bottom (schematic designator C6)
C7_M1 "10uF 10V" C0402 1989.1,2660 r0 top (schematic designator C7)
C7_M2 "10uF 10V" C0402 1999.1,1225 r0 top (schematic designator C7)
C8_M1 "10uF 10V" C0402 2086.85,2559.02 r270 bottom (schematic designator C8)
C8_M2 "10uF 10V" C0402 2088.9,1130.61 r270 bottom (schematic designator C8)
C9_M1 "10uF 10V" C0402 2361.85,2492.52 r0 bottom (schematic designator C9)
C9_M2 "10uF 10V" C0402 2363.9,1064.11 r0 bottom (schematic designator C9)
C10_M1 "0.1uF 50V" C0402 1989.1,2620 r0 top (schematic designator C10)
C10_M2 "0.1uF 50V" C0402 1998.49,1183.76 r0 top (schematic designator C10)
C11_M1 "0.1uF 50V" C0402 2108.35,2702.52 r180 bottom (schematic designator C11)
C11_M2 "0.1uF 50V" C0402 2110.4,1274.11 r180 bottom (schematic designator C11)
C12_M1 "0.1uF 50V" C0402 2296.85,2792.52 r180 bottom (schematic designator C12)
C12_M2 "0.1uF 50V" C0402 2298.9,1364.11 r180 bottom (schematic designator C12)
C13 "10uF 25V" C0603 3332.46,3342.53 r0 top
C14 "10nF 25V" C0402 3328.52,3232.53 r0 top
C15 "10nF 25V" C0402 3247.2,1877.52 r90 top
C16 "22uF 16V" C0603 2972.2,1725.86 r90 top
C17 "22uF 16V" C0603 2954.65,1878.42 r0 top
C18 "10nF 25V" C0402 2922.2,1712.52 r90 top
C19 "10nF 25V" C0402 3192.2,1877.52 r90 top
C20 "10uF 25V" C0603 3089.65,1948.42 r0 top
C21 "NA" C0402 3192.2,1774.32 r270 top
C22 "10nF 25V" C0402 3247.85,1532.08 r90 top
C23 "22uF 16V" C0603 2922.85,1367.08 r90 top
C24 "10nF 25V" C0402 3192.85,1532.08 r90 top
C25 "10nF 25V" C0402 3037.85,1360.42 r90 top
C26 "10uF 25V" C0603 2955.29,1532.98 r0 top
C27 "22uF 16V" C0603 3090.29,1602.98 r0 top
C28 "NA" C0402 3192.85,1428.88 r270 top
C29_LS1 "0.1uF 50V" C0402 2978.79,706.43 r180 top (schematic designator C29)
C29_LS2 "0.1uF 50V" C0402 2817.89,766.43 r180 top (schematic designator C29)
C29_LS3 "0.1uF 50V" C0402 3399.39,626.43 r180 bottom (schematic designator C29)
C29_LS4 "0.1uF 50V" C0402 3137.89,579.93 r90 bottom (schematic designator C29)
C30_LS1 "0.1uF 50V" C0402 2978.79,746.43 r180 top (schematic designator C30)
C30_LS2 "0.1uF 50V" C0402 2817.89,721.43 r180 top (schematic designator C30)
C30_LS3 "0.1uF 50V" C0402 3337.89,594.93 r90 bottom (schematic designator C30)
C30_LS4 "0.1uF 50V" C0402 3174.39,641.43 r180 bottom (schematic designator C30)
C31_A1 "1uF 25V" C0402 885,3165 r180 top (schematic designator C31)
C31_A2 "1uF 25V" C0402 885,2805.67 r180 top (schematic designator C31)
C31_A3 "1uF 25V" C0402 885,2451.34 r180 top (schematic designator C31)
C31_A4 "1uF 25V" C0402 885,2097.01 r180 top (schematic designator C31)
C31_A5 "1uF 25V" C0402 885,1742.68 r180 top (schematic designator C31)
C31_A6 "1uF 25V" C0402 885,1388.35 r180 top (schematic designator C31)
C31_A7 "1uF 25V" C0402 885,1035 r180 top (schematic designator C31)
C31_A8 "1uF 25V" C0402 885,680 r180 top (schematic designator C31)
C32_A1 "1uF 25V" C0402 1080,3080 r180 top (schematic designator C32)
C32_A2 "1uF 25V" C0402 1080,2720.67 r180 top (schematic designator C32)
C32_A3 "1uF 25V" C0402 1080,2366.34 r180 top (schematic designator C32)
C32_A4 "1uF 25V" C0402 1080,2012.01 r180 top (schematic designator C32)
C32_A5 "1uF 25V" C0402 1080,1657.68 r180 top (schematic designator C32)
C32_A6 "1uF 25V" C0402 1080,1303.35 r180 top (schematic designator C32)
C32_A7 "1uF 25V" C0402 1080,950 r180 top (schematic designator C32)
C32_A8 "1uF 25V" C0402 1080,595 r180 top (schematic designator C32)
C33_A1 "16pF 50V" C0402 746.83,3115.41 r270 top (schematic designator C33)
C33_A2 "16pF 50V" C0402 746.83,2756.08 r270 top (schematic designator C33)
C33_A3 "16pF 50V" C0402 746.83,2401.75 r270 top (schematic designator C33)
C33_A4 "16pF 50V" C0402 746.83,2047.42 r270 top (schematic designator C33)
C33_A5 "16pF 50V" C0402 746.83,1693.09 r270 top (schematic designator C33)
C33_A6 "16pF 50V" C0402 746.83,1338.76 r270 top (schematic designator C33)
C33_A7 "16pF 50V" C0402 746.83,985.41 r270 top (schematic designator C33)
C33_A8 "16pF 50V" C0402 746.83,630.41 r270 top (schematic designator C33)
C34_A1 "11pF 50V" C0402 661.83,3111.31 r270 top (schematic designator C34)
C34_A2 "11pF 50V" C0402 661.83,2751.98 r270 top (schematic designator C34)
C34_A3 "11pF 50V" C0402 661.83,2397.65 r270 top (schematic designator C34)
C34_A4 "11pF 50V" C0402 661.83,2043.32 r270 top (schematic designator C34)
C34_A5 "11pF 50V" C0402 661.83,1688.99 r270 top (schematic designator C34)
C34_A6 "11pF 50V" C0402 661.83,1334.66 r270 top (schematic designator C34)
C34_A7 "11pF 50V" C0402 661.83,981.31 r270 top (schematic designator C34)
C34_A8 "11pF 50V" C0402 661.83,626.31 r270 top (schematic designator C34)
C35_A1 "10pF 50V" C0402 581.83,3111.31 r270 top (schematic designator C35)
C35_A2 "10pF 50V" C0402 581.83,2751.98 r270 top (schematic designator C35)
C35_A3 "10pF 50V" C0402 581.83,2397.65 r270 top (schematic designator C35)
C35_A4 "10pF 50V" C0402 581.83,2043.32 r270 top (schematic designator C35)
C35_A5 "10pF 50V" C0402 581.83,1688.99 r270 top (schematic designator C35)
C35_A6 "10pF 50V" C0402 581.83,1334.66 r270 top (schematic designator C35)
C35_A7 "10pF 50V" C0402 581.83,981.31 r270 top (schematic designator C35)
C35_A8 "10pF 50V" C0402 581.83,626.31 r270 top (schematic designator C35)
C36_A1 "13pF 50V" C0402 506.83,3110.41 r270 top (schematic designator C36)
C36_A2 "13pF 50V" C0402 506.83,2751.08 r270 top (schematic designator C36)
C36_A3 "13pF 50V" C0402 506.83,2396.75 r270 top (schematic designator C36)
C36_A4 "13pF 50V" C0402 506.83,2042.42 r270 top (schematic designator C36)
C36_A5 "13pF 50V" C0402 506.83,1688.09 r270 top (schematic designator C36)
C36_A6 "13pF 50V" C0402 506.83,1333.76 r270 top (schematic designator C36)
C36_A7 "13pF 50V" C0402 506.83,980.41 r270 top (schematic designator C36)
C36_A8 "13pF 50V" C0402 506.83,625.41 r270 top (schematic designator C36)
C37_A1 "470pF 25V" C0402 1005,3139.33 r90 bottom (schematic designator C37)
C37_A2 "470pF 25V" C0402 1005,2780 r90 bottom (schematic designator C37)
C37_A3 "470pF 25V" C0402 1005,2425.67 r90 bottom (schematic designator C37)
C37_A4 "470pF 25V" C0402 1005,2071.34 r90 bottom (schematic designator C37)
C37_A5 "470pF 25V" C0402 1005,1717.01 r90 bottom (schematic designator C37)
C37_A6 "470pF 25V" C0402 1005,1362.68 r90 bottom (schematic designator C37)
C37_A7 "470pF 25V" C0402 1005,1009.33 r90 bottom (schematic designator C37)
C37_A8 "470pF 25V" C0402 1005,654.33 r90 bottom (schematic designator C37)
C38_A1 "0.1uF 50V" C0402 1045,3139.33 r90 bottom (schematic designator C38)
C38_A2 "0.1uF 50V" C0402 1045,2780 r90 bottom (schematic designator C38)
C38_A3 "0.1uF 50V" C0402 1045,2425.67 r90 bottom (schematic designator C38)
C38_A4 "0.1uF 50V" C0402 1045,2071.34 r90 bottom (schematic designator C38)
C38_A5 "0.1uF 50V" C0402 1045,1717.01 r90 bottom (schematic designator C38)
C38_A6 "0.1uF 50V" C0402 1045,1362.68 r90 bottom (schematic designator C38)
C38_A7 "0.1uF 50V" C0402 1045,1009.33 r90 bottom (schematic designator C38)
C38_A8 "0.1uF 50V" C0402 1045,654.33 r90 bottom (schematic designator C38)
C39_A1 "0.1uF 50V" C0402 1565,3033.82 r270 bottom (schematic designator C39)
C39_A2 "0.1uF 50V" C0402 1565,2674.49 r270 bottom (schematic designator C39)
C39_A3 "0.1uF 50V" C0402 1565,2320.15 r270 bottom (schematic designator C39)
C39_A4 "0.1uF 50V" C0402 1565,1965.82 r270 bottom (schematic designator C39)
C39_A5 "0.1uF 50V" C0402 1565,1611.49 r270 bottom (schematic designator C39)
C39_A6 "0.1uF 50V" C0402 1565,1257.16 r270 bottom (schematic designator C39)
C39_A7 "0.1uF 50V" C0402 1565,903.82 r270 bottom (schematic designator C39)
C39_A8 "0.1uF 50V" C0402 1565,548.82 r270 bottom (schematic designator C39)
C40_A1 "1uF 25V" C0402 1545,2973.82 r0 bottom (schematic designator C40)
C40_A2 "1uF 25V" C0402 1545,2614.49 r0 bottom (schematic designator C40)
C40_A3 "1uF 25V" C0402 1545,2260.15 r0 bottom (schematic designator C40)
C40_A4 "1uF 25V" C0402 1545,1905.82 r0 bottom (schematic designator C40)
C40_A5 "1uF 25V" C0402 1545,1551.49 r0 bottom (schematic designator C40)
C40_A6 "1uF 25V" C0402 1545,1197.16 r0 bottom (schematic designator C40)
C40_A7 "1uF 25V" C0402 1545,843.82 r0 bottom (schematic designator C40)
C40_A8 "1uF 25V" C0402 1545,488.82 r0 bottom (schematic designator C40)
C41_M1 "0.1uF 50V" C0402 1985.06,3165 r180 bottom (schematic designator C41)
C41_M2 "0.1uF 50V" C0402 1985.06,1790 r180 bottom (schematic designator C41)
C42_M1 "0.1uF 50V" C0402 1985.06,3210 r180 bottom (schematic designator C42)
C42_M2 "0.1uF 50V" C0402 1985.06,1744.98 r180 bottom (schematic designator C42)
C43_M1 "10uF 10V" C0402 1985.06,3120 r180 bottom (schematic designator C43)
C43_M2 "10uF 10V" C0402 1985.06,1700 r180 bottom (schematic designator C43)
C57_M1 "0.1uF 50V" C0402 1985.06,2860 r180 bottom (schematic designator C57)
C57_M2 "0.1uF 50V" C0402 1985.06,1440 r180 bottom (schematic designator C57)
C58_M1 "0.1uF 50V" C0402 1985.06,2815 r180 bottom (schematic designator C58)
C58_M2 "0.1uF 50V" C0402 1985.06,1394.98 r180 bottom (schematic designator C58)
C59_M1 "10uF 10V" C0402 1985.06,2770 r180 bottom (schematic designator C59)
C59_M2 "10uF 10V" C0402 1985.06,1350 r180 bottom (schematic designator C59)
C60_M1 "0.1uF 50V" C0402 1985.06,2495 r180 bottom (schematic designator C60)
C60_M2 "0.1uF 50V" C0402 1985.06,1066.5 r180 bottom (schematic designator C60)
C61_M1 "0.1uF 50V" C0402 1985.06,2450 r180 bottom (schematic designator C61)
C61_M2 "0.1uF 50V" C0402 1985.06,1021.5 r180 bottom (schematic designator C61)
C62_M1 "10uF 10V" C0402 1985.06,2405 r180 bottom (schematic designator C62)
C62_M2 "10uF 10V" C0402 1985.06,976.5 r180 bottom (schematic designator C62)
C63_M1 "0.1uF 50V" C0402 1985.06,2145 r180 bottom (schematic designator C63)
C63_M2 "0.1uF 50V" C0402 1985.06,721.5 r180 bottom (schematic designator C63)
C64_M1 "0.1uF 50V" C0402 1985.06,2100 r180 bottom (schematic designator C64)
C64_M2 "0.1uF 50V" C0402 1985.06,676.48 r180 bottom (schematic designator C64)
C65_M1 "10uF 10V" C0402 1985.06,2055 r180 bottom (schematic designator C65)
C65_M2 "10uF 10V" C0402 1985.06,631.5 r180 bottom (schematic designator C65)
F1 "PTC 24V / 1.5A" 1812_F 2420,582.44 r90 top
F2 "PTC 24V / 1.5A" 1812_F 2565,582.44 r90 top
F3 "PTC 24V / 1.5A" 1812_F 2275,582.44 r270 top
FB1_M1 "BLM18EG221SN1D" FB0603 2259.41,2497.52 r180 bottom (schematic designator FB1)
FB1_M2 "BLM18EG221SN1D" FB0603 2261.46,1069.11 r180 bottom (schematic designator FB1)
FB2 "BLM18EG221SN1D" FB0603 3219.76,1948.42 r180 top
FB3 "BLM18EG221SN1D" FB0603 2954.65,1793.42 r180 top
FB4 "BLM18EG221SN1D" FB0603 3220.41,1602.98 r180 top
FB5 "BLM18EG221SN1D" FB0603 2955.29,1447.98 r180 top
FB6_A1 "BLM15HD182" 0402-A 1139.69,3200 r180 bottom (schematic designator FB6)
FB6_A2 "BLM15HD182" 0402-A 1140,2845 r180 bottom (schematic designator FB6)
FB6_A3 "BLM15HD182" 0402-A 1139.69,2490 r180 bottom (schematic designator FB6)
FB6_A4 "BLM15HD182" 0402-A 1139.69,2135 r180 bottom (schematic designator FB6)
FB6_A5 "BLM15HD182" 0402-A 1140,1780 r180 bottom (schematic designator FB6)
FB6_A6 "BLM15HD182" 0402-A 1139.69,1425 r180 bottom (schematic designator FB6)
FB6_A7 "BLM15HD182" 0402-A 1139.69,1070 r180 bottom (schematic designator FB6)
FB6_A8 "BLM15HD182" 0402-A 1140,715 r180 bottom (schematic designator FB6)
FID1 "Fiducial" FIDUCIAL 2860,3362.52 r90 top
FID2 "Fiducial" FIDUCIAL 3705,517.52 r90 top
FID3 "Fiducial" FIDUCIAL 435,292.52 r90 top
FID4 "Fiducial" FIDUCIAL 2865,3362.52 r90 bottom
FID5 "Fiducial" FIDUCIAL 3710,517.52 r90 bottom
FID6 "Fiducial" FIDUCIAL 445,292.52 r90 bottom
H1 "Hole 3mm" "HOLE 3MM" 3848.91,3090.92 r0 top
H2 "Hole 3mm" "HOLE 3MM" 187.5,3327.14 r0 top
H3 "Hole 3mm" "HOLE 3MM" 3848.91,590.92 r0 top
H4 "Hole 3mm" "HOLE 3MM" 187.5,315.33 r0 top
J1 "1053141204" CON_1053141204 3486.59,3347.53 r90 top
J2 "5767096-1" MICTOR-38_PIN 3477.4,2707.71 r90 top
J3 "90131-0770" HEADER_10X2 2654.39,3012.53 r270 top
J4 "90131-0770" HEADER_10X2 3234.39,3007.53 r270 top
J5 "90131-0770" HEADER_10X2 2949.39,3012.53 r270 top
J6 "10018784-10201TLF" PCIE_8LANE_EDGE 2810.18,256.72 r0 top locked
J7_A1 "SMA-J-P-H-RA-TH1" CONN_SMA-J-P-H-RA-TH1_SAI 180,3095 r90 top (schematic designator J7)
J7_A2 "SMA-J-P-H-RA-TH1" CONN_SMA-J-P-H-RA-TH1_SAI 180,2735.67 r270 bottom (schematic designator J7)
J7_A3 "SMA-J-P-H-RA-TH1" CONN_SMA-J-P-H-RA-TH1_SAI 180,2381.34 r90 top (schematic designator J7)
J7_A4 "SMA-J-P-H-RA-TH1" CONN_SMA-J-P-H-RA-TH1_SAI 180,2027.01 r270 bottom (schematic designator J7)
J7_A5 "SMA-J-P-H-RA-TH1" CONN_SMA-J-P-H-RA-TH1_SAI 180,1672.68 r90 top (schematic designator J7)
J7_A6 "SMA-J-P-H-RA-TH1" CONN_SMA-J-P-H-RA-TH1_SAI 180,1318.35 r270 bottom (schematic designator J7)
J7_A7 "SMA-J-P-H-RA-TH1" CONN_SMA-J-P-H-RA-TH1_SAI 180,965 r90 top (schematic designator J7)
J7_A8 "SMA-J-P-H-RA-TH1" CONN_SMA-J-P-H-RA-TH1_SAI 180,610 r270 bottom (schematic designator J7)
J8_A1 "MMCX-J-P-H-ST-TH1" SAMTEC_MMCX-J-P-H-ST-TH1 1505,3205 r270 top (schematic designator J8)
J8_A2 "MMCX-J-P-H-ST-TH1" SAMTEC_MMCX-J-P-H-ST-TH1 1505,2845.67 r270 top (schematic designator J8)
J8_A3 "MMCX-J-P-H-ST-TH1" SAMTEC_MMCX-J-P-H-ST-TH1 1505,2491.34 r270 top (schematic designator J8)
J8_A4 "MMCX-J-P-H-ST-TH1" SAMTEC_MMCX-J-P-H-ST-TH1 1505,2137.01 r270 top (schematic designator J8)
J8_A5 "MMCX-J-P-H-ST-TH1" SAMTEC_MMCX-J-P-H-ST-TH1 1505,1782.68 r270 top (schematic designator J8)
J8_A6 "MMCX-J-P-H-ST-TH1" SAMTEC_MMCX-J-P-H-ST-TH1 1505,1428.35 r270 top (schematic designator J8)
J8_A7 "MMCX-J-P-H-ST-TH1" SAMTEC_MMCX-J-P-H-ST-TH1 1505,1075 r270 top (schematic designator J8)
J8_A8 "MMCX-J-P-H-ST-TH1" SAMTEC_MMCX-J-P-H-ST-TH1 1505,720 r270 top (schematic designator J8)
L1_A1 "Inductor" 0402-A 706.83,3165.41 r180 top value=56nH (schematic designator L1)
L1_A2 "Inductor" 0402-A 706.83,2806.08 r180 top value=56nH (schematic designator L1)
L1_A3 "Inductor" 0402-A 706.83,2451.75 r180 top value=56nH (schematic designator L1)
L1_A4 "Inductor" 0402-A 706.83,2097.42 r180 top value=56nH (schematic designator L1)
L1_A5 "Inductor" 0402-A 706.83,1743.09 r180 top value=56nH (schematic designator L1)
L1_A6 "Inductor" 0402-A 706.83,1388.76 r180 top value=56nH (schematic designator L1)
L1_A7 "Inductor" 0402-A 706.83,1035.41 r180 top value=56nH (schematic designator L1)
L1_A8 "Inductor" 0402-A 706.83,680.41 r180 top value=56nH (schematic designator L1)
L2_A1 "Inductor" 0402-A 791.52,3165.41 r180 top value=43nH (schematic designator L2)
L2_A2 "Inductor" 0402-A 791.52,2806.08 r180 top value=43nH (schematic designator L2)
L2_A3 "Inductor" 0402-A 791.52,2451.75 r180 top value=43nH (schematic designator L2)
L2_A4 "Inductor" 0402-A 791.52,2097.42 r180 top value=43nH (schematic designator L2)
L2_A5 "Inductor" 0402-A 791.52,1743.09 r180 top value=43nH (schematic designator L2)
L2_A6 "Inductor" 0402-A 791.52,1388.76 r180 top value=43nH (schematic designator L2)
L2_A7 "Inductor" 0402-A 791.52,1035.41 r180 top value=43nH (schematic designator L2)
L2_A8 "Inductor" 0402-A 791.52,680.41 r180 top value=43nH (schematic designator L2)
L3_A1 "Inductor" 0402-A 621.83,3165.41 r180 top value=43nH (schematic designator L3)
L3_A2 "Inductor" 0402-A 621.83,2806.08 r180 top value=43nH (schematic designator L3)
L3_A3 "Inductor" 0402-A 621.83,2451.75 r180 top value=43nH (schematic designator L3)
L3_A4 "Inductor" 0402-A 621.83,2097.42 r180 top value=43nH (schematic designator L3)
L3_A5 "Inductor" 0402-A 621.83,1743.09 r180 top value=43nH (schematic designator L3)
L3_A6 "Inductor" 0402-A 621.83,1388.76 r180 top value=43nH (schematic designator L3)
L3_A7 "Inductor" 0402-A 621.83,1035.41 r180 top value=43nH (schematic designator L3)
L3_A8 "Inductor" 0402-A 621.83,680.41 r180 top value=43nH (schematic designator L3)
L4_A1 "Inductor" 0402-A 541.83,3165.41 r180 top value=47nH (schematic designator L4)
L4_A2 "Inductor" 0402-A 541.83,2806.08 r180 top value=47nH (schematic designator L4)
L4_A3 "Inductor" 0402-A 541.83,2451.75 r180 top value=47nH (schematic designator L4)
L4_A4 "Inductor" 0402-A 541.83,2097.42 r180 top value=47nH (schematic designator L4)
L4_A5 "Inductor" 0402-A 541.83,1743.09 r180 top value=47nH (schematic designator L4)
L4_A6 "Inductor" 0402-A 541.83,1388.76 r180 top value=47nH (schematic designator L4)
L4_A7 "Inductor" 0402-A 541.83,1035.41 r180 top value=47nH (schematic designator L4)
L4_A8 "Inductor" 0402-A 541.83,680.41 r180 top value=47nH (schematic designator L4)
L5_A1 "Inductor" 0402-A 456.83,3165.41 r180 top value=33nH (schematic designator L5)
L5_A2 "Inductor" 0402-A 456.83,2806.08 r180 top value=33nH (schematic designator L5)
L5_A3 "Inductor" 0402-A 456.83,2451.75 r180 top value=33nH (schematic designator L5)
L5_A4 "Inductor" 0402-A 456.83,2097.42 r180 top value=33nH (schematic designator L5)
L5_A5 "Inductor" 0402-A 456.83,1743.09 r180 top value=33nH (schematic designator L5)
L5_A6 "Inductor" 0402-A 456.83,1388.76 r180 top value=33nH (schematic designator L5)
L5_A7 "Inductor" 0402-A 456.83,1035.41 r180 top value=33nH (schematic designator L5)
L5_A8 "Inductor" 0402-A 456.83,680.41 r180 top value=33nH (schematic designator L5)
L6_A1 "Inductor" 0402-A 661.83,3025.73 r270 top value=24nH (schematic designator L6)
L6_A2 "Inductor" 0402-A 661.83,2666.4 r270 top value=24nH (schematic designator L6)
L6_A3 "Inductor" 0402-A 661.83,2312.07 r270 top value=24nH (schematic designator L6)
L6_A4 "Inductor" 0402-A 661.83,1957.74 r270 top value=24nH (schematic designator L6)
L6_A5 "Inductor" 0402-A 661.83,1603.41 r270 top value=24nH (schematic designator L6)
L6_A6 "Inductor" 0402-A 661.83,1249.07 r270 top value=24nH (schematic designator L6)
L6_A7 "Inductor" 0402-A 661.83,895.73 r270 top value=24nH (schematic designator L6)
L6_A8 "Inductor" 0402-A 661.83,540.73 r270 top value=24nH (schematic designator L6)
L7_A1 "Inductor" 0402-A 581.83,3025.73 r270 top value=33nH (schematic designator L7)
L7_A2 "Inductor" 0402-A 581.83,2666.4 r270 top value=33nH (schematic designator L7)
L7_A3 "Inductor" 0402-A 581.83,2312.07 r270 top value=33nH (schematic designator L7)
L7_A4 "Inductor" 0402-A 581.83,1957.74 r270 top value=33nH (schematic designator L7)
L7_A5 "Inductor" 0402-A 581.83,1603.41 r270 top value=33nH (schematic designator L7)
L7_A6 "Inductor" 0402-A 581.83,1249.07 r270 top value=33nH (schematic designator L7)
L7_A7 "Inductor" 0402-A 581.83,895.73 r270 top value=33nH (schematic designator L7)
L7_A8 "Inductor" 0402-A 581.83,540.73 r270 top value=33nH (schematic designator L7)
L8_A1 "Inductor" 0402-A 506.83,3020.41 r270 top value=15nH (schematic designator L8)
L8_A2 "Inductor" 0402-A 506.83,2661.08 r270 top value=15nH (schematic designator L8)
L8_A3 "Inductor" 0402-A 506.83,2306.75 r270 top value=15nH (schematic designator L8)
L8_A4 "Inductor" 0402-A 506.83,1952.42 r270 top value=15nH (schematic designator L8)
L8_A5 "Inductor" 0402-A 506.83,1598.09 r270 top value=15nH (schematic designator L8)
L8_A6 "Inductor" 0402-A 506.83,1243.76 r270 top value=15nH (schematic designator L8)
L8_A7 "Inductor" 0402-A 506.83,890.41 r270 top value=15nH (schematic designator L8)
L8_A8 "Inductor" 0402-A 506.83,535.41 r270 top value=15nH (schematic designator L8)
L9_A1 "Inductor" 0402-A 746.83,3025.73 r270 top value=3.9nH (schematic designator L9)
L9_A2 "Inductor" 0402-A 746.83,2666.4 r270 top value=3.9nH (schematic designator L9)
L9_A3 "Inductor" 0402-A 746.83,2312.07 r270 top value=3.9nH (schematic designator L9)
L9_A4 "Inductor" 0402-A 746.83,1957.74 r270 top value=3.9nH (schematic designator L9)
L9_A5 "Inductor" 0402-A 746.83,1603.41 r270 top value=3.9nH (schematic designator L9)
L9_A6 "Inductor" 0402-A 746.83,1249.07 r270 top value=3.9nH (schematic designator L9)
L9_A7 "Inductor" 0402-A 746.83,895.73 r270 top value=3.9nH (schematic designator L9)
L9_A8 "Inductor" 0402-A 746.83,540.73 r270 top value=3.9nH (schematic designator L9)
LD1 "APT1608SGC" LED_0603_GREEN 2759.37,1875.5 r90 top
LD2 "APT1608SGC" LED_0603_GREEN 2760.02,1530.06 r90 top
Lp1 "NR6028T100M" IND6X6_H3 3544.65,1662.52 r180 top
R1_M1 "6.8K" R0402 2361.85,2547.52 r0 bottom (schematic designator R1)
R1_M2 "6.8K" R0402 2363.9,1119.11 r0 bottom (schematic designator R1)
R2_M1 "0R" R0402 2366.85,2752.52 r180 bottom (schematic designator R2)
R2_M2 "0R" R0402 2368.9,1324.11 r180 bottom (schematic designator R2)
R3_M1 "10K" R0402 3460,750.9 r270 top (schematic designator R3)
R3_M2 "10K" R0402 3235,755 r270 top (schematic designator R3)
R4_M1 "10K" R0402 3420,750.9 r270 top (schematic designator R4)
R4_M2 "10K" R0402 3195,755 r270 top (schematic designator R4)
R5_M1 "10K" R0402 3380,750.9 r270 top (schematic designator R5)
R5_M2 "10K" R0402 3155,755 r270 top (schematic designator R5)
R6_M1 "10K" R0402 3340,750.9 r270 top (schematic designator R6)
R6_M2 "10K" R0402 3115,755 r270 top (schematic designator R6)
R7_M1 "NA" R0402 2088.35,2492.52 r180 bottom (schematic designator R7)
R7_M2 "NA" R0402 2090.4,1064.11 r180 bottom (schematic designator R7)
R8_M1 "0R" R0402 2386.85,2614.02 r270 bottom (schematic designator R8)
R8_M2 "0R" R0402 2388.9,1185.61 r270 bottom (schematic designator R8)
R9_M1 "0R" R0402 2146.85,2513.42 r270 bottom (schematic designator R9)
R9_M2 "0R" R0402 2148.9,1085.01 r270 bottom (schematic designator R9)
R10_M1 "NA" R0402 2365.35,2672.52 r0 bottom (schematic designator R10)
R10_M2 "NA" R0402 2367.4,1244.11 r0 bottom (schematic designator R10)
R11_M1 "10K" R0402 2206.85,2762.52 r90 bottom (schematic designator R11)
R11_M2 "10K" R0402 2208.9,1334.11 r90 bottom (schematic designator R11)
R12_M1 "10K" R0402 2166.85,2762.52 r90 bottom (schematic designator R12)
R12_M2 "10K" R0402 2168.9,1334.11 r90 bottom (schematic designator R12)
R13_M1 "10K" R0402 2126.85,2762.52 r90 bottom (schematic designator R13)
R13_M2 "10K" R0402 2128.9,1334.11 r90 bottom (schematic designator R13)
R14_M1 "10K" R0402 2086.85,2762.52 r90 bottom (schematic designator R14)
R14_M2 "10K" R0402 2088.9,1334.11 r90 bottom (schematic designator R14)
R15_M1 "0R" R0805 1848.83,2027.47 r0 bottom (schematic designator R15)
R15_M2 "0R" R0805 1811.24,605.23 r0 bottom (schematic designator R15)
R16_M1 "0R" R0805 1811.24,2522.47 r0 bottom (schematic designator R16)
R16_M2 "0R" R0805 1811.24,1090.23 r0 bottom (schematic designator R16)
R17_M1 "0R" R0805 1811.24,2882.47 r0 bottom (schematic designator R17)
R17_M2 "0R" R0805 1811.24,1463.73 r0 bottom (schematic designator R17)
R18_M1 "0R" R0805 1811.24,3092.47 r0 bottom (schematic designator R18)
R18_M2 "0R" R0805 1811.24,1673.73 r0 bottom (schematic designator R18)
R19_M1 "0R" R0805 1848.83,2167.47 r0 bottom (schematic designator R19)
R19_M2 "0R" R0805 1848.83,745.23 r0 bottom (schematic designator R19)
R20_M1 "0R" R0805 1811.24,2452.47 r0 bottom (schematic designator R20)
R20_M2 "0R" R0805 1811.24,1020.23 r0 bottom (schematic designator R20)
R21_M1 "0R" R0805 1811.24,2742.47 r0 bottom (schematic designator R21)
R21_M2 "0R" R0805 1811.24,1323.73 r0 bottom (schematic designator R21)
R22_M1 "0R" R0805 1811.24,3162.47 r0 bottom (schematic designator R22)
R22_M2 "0R" R0805 1811.24,1743.73 r0 bottom (schematic designator R22)
R23_M1 "0R" R0805 1848.83,2097.47 r0 bottom (schematic designator R23)
R23_M2 "0R" R0805 1848.83,675.23 r0 bottom (schematic designator R23)
R24_M1 "0R" R0805 1811.24,2387.47 r0 bottom (schematic designator R24)
R24_M2 "0R" R0805 1811.24,955.23 r0 bottom (schematic designator R24)
R25_M1 "0R" R0805 1811.24,2812.47 r0 bottom (schematic designator R25)
R25_M2 "0R" R0805 1811.24,1393.73 r0 bottom (schematic designator R25)
R26_M1 "0R" R0805 1811.24,3232.47 r0 bottom (schematic designator R26)
R26_M2 "0R" R0805 1811.24,1813.73 r0 bottom (schematic designator R26)
R27 "124K" R0402 3087.2,1714.32 r270 top
R28 "1K" R0402 2757.2,1784.92 r270 top
R29 "39.2K" R0402 3127.2,1712.52 r90 top
R30 "124K" R0402 3087.85,1368.88 r270 top
R31 "1K" R0402 2757.85,1439.48 r270 top
R32 "100K" R0402 3127.85,1367.08 r90 top
R33 "0R" R0402 2115,1885 r90 top
R34_LS1 "100K" R0402 2907.89,656.43 r270 top (schematic designator R34)
R34_LS2 "100K" R0402 2737.89,651.43 r90 top (schematic designator R34)
R34_LS3 "100K" R0402 3292.89,656.43 r90 top (schematic designator R34)
R34_LS4 "100K" R0402 3087.89,651.43 r90 top (schematic designator R34)
R35_LS1 "NA" R0402 2907.89,571.43 r90 top (schematic designator R35)
R35_LS2 "NA" R0402 2737.89,564.93 r90 top (schematic designator R35)
R35_LS3 "NA" R0402 3292.89,570.53 r90 top (schematic designator R35)
R35_LS4 "NA" R0402 3087.89,566.43 r90 top (schematic designator R35)
R36_A1 "34.8R" R0402 1264.12,3079.59 r0 top (schematic designator R36)
R36_A2 "34.8R" R0402 1264.12,2720.26 r0 top (schematic designator R36)
R36_A3 "34.8R" r0402 1264.12,2365.93 r0 top (schematic designator R36)
R36_A4 "34.8R" r0402 1264.12,2011.59 r0 top (schematic designator R36)
R36_A5 "34.8R" R0402 1264.12,1657.26 r0 top (schematic designator R36)
R36_A6 "34.8R" R0402 1264.12,1302.93 r0 top (schematic designator R36)
R36_A7 "34.8R" r0402 1264.12,949.59 r0 top (schematic designator R36)
R36_A8 "34.8R" r0402 1264.12,594.59 r0 top (schematic designator R36)
R37_A1 "34.8R" R0402 1152.49,3079.57 r0 top (schematic designator R37)
R37_A2 "34.8R" R0402 1152.49,2720.24 r0 top (schematic designator R37)
R37_A3 "34.8R" r0402 1152.49,2365.91 r0 top (schematic designator R37)
R37_A4 "34.8R" r0402 1152.49,2011.58 r0 top (schematic designator R37)
R37_A5 "34.8R" R0402 1152.49,1657.25 r0 top (schematic designator R37)
R37_A6 "34.8R" R0402 1152.49,1302.92 r0 top (schematic designator R37)
R37_A7 "34.8R" r0402 1152.49,949.57 r0 top (schematic designator R37)
R37_A8 "34.8R" r0402 1152.49,594.57 r0 top (schematic designator R37)
R38_A1 "18.2R" R0402 1210,3061.5 r270 top (schematic designator R38)
R38_A2 "18.2R" R0402 1210,2702.17 r270 top (schematic designator R38)
R38_A3 "18.2R" r0402 1210,2347.84 r270 top (schematic designator R38)
R38_A4 "18.2R" r0402 1210,1993.51 r270 top (schematic designator R38)
R38_A5 "18.2R" R0402 1210,1639.18 r270 top (schematic designator R38)
R38_A6 "18.2R" R0402 1210,1284.85 r270 top (schematic designator R38)
R38_A7 "18.2R" r0402 1210,931.5 r270 top (schematic designator R38)
R38_A8 "18.2R" r0402 1210,576.5 r270 top (schematic designator R38)
R39_M1 "49.9R" R0402 1958.11,3083.5 r90 top (schematic designator R39)
R39_M2 "49.9R" R0402 1958.11,1663.5 r90 top (schematic designator R39)
R40_M1 "49.9R" R0402 1958.11,3244.1 r90 top (schematic designator R40)
R40_M2 "49.9R" R0402 1958.11,1824.1 r90 top (schematic designator R40)
R41_A1 "NA" R0402 1285,3140.9 r270 top (schematic designator R41)
R41_A2 "NA" R0402 1285,2781.57 r270 top (schematic designator R41)
R41_A3 "NA" r0402 1285,2427.24 r270 top (schematic designator R41)
R41_A4 "NA" r0402 1285,2072.91 r270 top (schematic designator R41)
R41_A5 "NA" R0402 1285,1718.58 r270 top (schematic designator R41)
R41_A6 "NA" R0402 1285,1364.25 r270 top (schematic designator R41)
R41_A7 "NA" r0402 1285,1010.9 r270 top (schematic designator R41)
R41_A8 "NA" r0402 1285,655.9 r270 top (schematic designator R41)
R42_A1 "4.7R" r0402 1065,3200 r180 bottom (schematic designator R42)
R42_A2 "4.7R" r0402 1065,2845 r180 bottom (schematic designator R42)
R42_A3 "4.7R" r0402 1065.9,2490 r180 bottom (schematic designator R42)
R42_A4 "4.7R" r0402 1065.9,2135 r180 bottom (schematic designator R42)
R42_A5 "4.7R" r0402 1065.9,1780 r180 bottom (schematic designator R42)
R42_A6 "4.7R" r0402 1065.9,1425 r180 bottom (schematic designator R42)
R42_A7 "4.7R" r0402 1065.9,1070 r180 bottom (schematic designator R42)
R42_A8 "4.7R" r0402 1065.9,715 r180 bottom (schematic designator R42)
R50_M1 "49.9R" R0402 1958.11,2733.5 r90 top (schematic designator R50)
R50_M2 "49.9R" R0402 1958.11,1313.5 r90 top (schematic designator R50)
R51_M1 "49.9R" R0402 1958.11,2894.1 r90 top (schematic designator R51)
R51_M2 "49.9R" R0402 1958.11,1474.1 r90 top (schematic designator R51)
R52_M1 "49.9R" R0402 1958.11,2531.5 r270 top (schematic designator R52)
R52_M2 "49.9R" R0402 1958.11,938.5 r90 top (schematic designator R52)
R53_M1 "49.9R" R0402 1958.11,2370.9 r270 top (schematic designator R53)
R53_M2 "49.9R" R0402 1958.11,1099.1 r90 top (schematic designator R53)
R54_M1 "49.9R" R0402 1958.11,2181.5 r270 top (schematic designator R54)
R54_M2 "49.9R" R0402 1958.11,756.5 r270 top (schematic designator R54)
R55_M1 "49.9R" R0402 1958.11,2020.9 r270 top (schematic designator R55)
R55_M2 "49.9R" R0402 1958.11,595.9 r270 top (schematic designator R55)
SH1_A1 "G-0300SB1000-0100XC" RF_Sh 867.5,3095 r0 top locked (schematic designator SH1)
SH1_A2 "G-0300SB1000-0100XC" RF_Sh 867.5,2735 r0 top locked (schematic designator SH1)
SH1_A3 "G-0300SB1000-0100XC" RF_Sh 867.5,2380 r0 top locked (schematic designator SH1)
SH1_A4 "G-0300SB1000-0100XC" RF_Sh 870,2025 r0 top locked (schematic designator SH1)
SH1_A5 "G-0300SB1000-0100XC" RF_Sh 870,1670 r0 top locked (schematic designator SH1)
SH1_A6 "G-0300SB1000-0100XC" RF_Sh 870,1315 r0 top locked (schematic designator SH1)
SH1_A7 "G-0300SB1000-0100XC" RF_Sh 870,965 r0 top locked (schematic designator SH1)
SH1_A8 "G-0300SB1000-0100XC" RF_Sh 870,610 r0 top locked (schematic designator SH1)
T1_M1 "ADTT1-1+" CD542_MNC 1782.02,3165 r180 top (schematic designator T1)
T1_M2 "ADTT1-1+" CD542_MNC 1782.02,1745 r180 top (schematic designator T1)
T3_M1 "ADTT1-1+" CD542_MNC 1782.02,2815 r180 top (schematic designator T3)
T3_M2 "ADTT1-1+" CD542_MNC 1782.02,1395 r180 top (schematic designator T3)
T4_M1 "ADTT1-1+" CD542_MNC 1782.02,2450 r180 top (schematic designator T4)
T4_M2 "ADTT1-1+" CD542_MNC 1782.02,1021.5 r180 top (schematic designator T4)
T5_M1 "ADTT1-1+" CD542_MNC 1782.02,2100 r180 top (schematic designator T5)
T5_M2 "ADTT1-1+" CD542_MNC 1782.02,676.5 r180 top (schematic designator T5)
TP1 "+12V" TP_2X1.8 3425,1432.52 r270 top
TP2 "+3.3V" TP_2X1.8 2847.2,1793.42 r90 top
TP3 "+1.8V" TP_2X1.8 2847.85,1447.98 r90 top
TP4 "SyncIn" TP_2X1.8 2405,2295 r90 top
TP5 "SyncOut" TP_2X1.8 2415,837.52 r270 top
TP6 "GND" TP_2X1.8 3860,2892.52 r270 top
TP7 "GND" TP_2X1.8 3855,747.52 r0 top
U1_M1 "AD9959BCPZ" CP_56_1_ADI 2236.85,2642.52 r90 top (schematic designator U1)
U1_M2 "AD9959BCPZ" CP_56_1_ADI 2238.9,1214.11 r90 top (schematic designator U1)
U2 "MUN12AD03-SEC" SO8_MUN12AD_DEA 3095,1832.52 r270 top
U3 "MUN12AD03-SEC" SO8_MUN12AD_DEA 3095.65,1487.08 r270 top
U4_LS1 "74AVC4T774_GU" NXP_74AVC4T245GU,115 2999.27,599.82 r90 top (schematic designator U4)
U4_LS2 "74AVC4T774_GU" NXP_74AVC4T245GU,115 2822.89,599.82 r90 top (schematic designator U4)
U4_LS3 "74AVC4T774_GU" NXP_74AVC4T245GU,115 3377.89,599.82 r90 top (schematic designator U4)
U4_LS4 "74AVC4T774_GU" NXP_74AVC4T245GU,115 3177.89,599.82 r90 top (schematic designator U4)
U5_A1 "BGA2815,115" SOT_2815,115_NXP 985.43,3121.89 r270 top (schematic designator U5)
U5_A2 "BGA2815,115" SOT_2815,115_NXP 985.59,2758.11 r270 top (schematic designator U5)
U5_A3 "BGA2815,115" SOT_2815,115_NXP 985.59,2408.11 r270 top (schematic designator U5)
U5_A4 "BGA2815,115" SOT_2815,115_NXP 985.59,2053.11 r270 top (schematic designator U5)
U5_A5 "BGA2815,115" SOT_2815,115_NXP 985.59,1698.11 r270 top (schematic designator U5)
U5_A6 "BGA2815,115" SOT_2815,115_NXP 985.59,1343.11 r270 top (schematic designator U5)
U5_A7 "BGA2815,115" SOT_2815,115_NXP 985.59,993.11 r270 top (schematic designator U5)
U5_A8 "BGA2815,115" SOT_2815,115_NXP 985.59,638.11 r270 top (schematic designator U5)
U6_A1 "ADG901BCPZ-500RL7" CP_8_2_ADI 1505,3032.52 r180 top (schematic designator U6)
U6_A2 "ADG901BCPZ-500RL7" CP_8_2_ADI 1505,2673.19 r180 top (schematic designator U6)
U6_A3 "ADG901BCPZ-500RL7" CP_8_2_ADI 1505,2318.86 r180 top (schematic designator U6)
U6_A4 "ADG901BCPZ-500RL7" CP_8_2_ADI 1505,1964.52 r180 top (schematic designator U6)
U6_A5 "ADG901BCPZ-500RL7" CP_8_2_ADI 1505,1610.19 r180 top (schematic designator U6)
U6_A6 "ADG901BCPZ-500RL7" CP_8_2_ADI 1505,1255.86 r180 top (schematic designator U6)
U6_A7 "ADG901BCPZ-500RL7" CP_8_2_ADI 1505,902.52 r180 top (schematic designator U6)
U6_A8 "ADG901BCPZ-500RL7" CP_8_2_ADI 1505,547.52 r180 top (schematic designator U6)
Y1_M1 "ECS-250-20-33-CKM-TR3" SMD4_ECX-32_3P2X2P5_ECS 2500.4,2597.24 r0 bottom (schematic designator Y1)
Y1_M2 "ECS-250-20-33-CKM-TR3" SMD4_ECX-32_3P2X2P5_ECS 2529.75,1216 r0 bottom (schematic designator Y1)

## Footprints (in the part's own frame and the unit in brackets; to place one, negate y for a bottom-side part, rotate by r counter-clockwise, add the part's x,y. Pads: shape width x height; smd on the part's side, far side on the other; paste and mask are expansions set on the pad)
0402-A [mm] "Chip Inductor, Body 1.0x0.5mm, IPC High Density"
  rect 0.6x0.5 smd mask+0.051: 1(-0.5,0) 2(0.5,0)
  silkscreen extent -1.1,-0.15 -1.1,0.15, body extent -0.55,-0.3 0.55,0.3, height 0.55
1812_F [mm] "PTC RESETTABLE 33V 1.10A 1812L"
  rect 1.78x3.15 smd mask+0.051: 1(-2.665,0) 2(2.665,0)
  silkscreen extent -2.4,-1.7 2.4,1.7, body extent -2.36,-1.74 2.37,1.74, height 1.03
C0402 [mil]
  rect 25x25 smd mask+2: 1(-18.5,0) 2(20.9,0)
  silkscreen extent -36,-17 40,17, body extent -20,-12 20,12, height 8
C0603 [mm]
  rect 0.7x0.9 smd mask+0.051: 1(-0.7,0) 2(0.7,0)
  silkscreen extent -1.2,-0.6 1.2,0.6, body extent -0.8,-0.4 0.8,0.4, height 0.3
CD542_MNC [mil]
  rect 37.81x28.03 smd paste+0 mask+2: 1(-128.91,100) 2(-128.91,0) 3(-128.91,-100) 4(128.91,-100) 5(128.91,0) 6(128.91,100)
  silkscreen extent -115,-160 115,160, body extent -136,-155 136,155, height 112
CON_1053141204 [mm]
  rect 1.7x1.7 hole 1.2 mask+0.076: 1(0,0)
  round 1.7 hole 1.2 mask+0.076: 2(-2.5,0) 3(0,-2.5) 4(-2.5,-2.5)
  round 1.6 hole 1.6 unplated mask+0.076: 5(0,-9.68) 6(-2.5,-9.68)
  silkscreen extent -4.22,-12.88 3.5,0.64, body extent -4.24,-14.2 1.7,0.46, height 8.85
CONN_SMA-J-P-H-RA-TH1_SAI [mil]
  round 83 hole 63 mask+0: 1(0,0) 2(-100,100) 3(-100,-100) 4(100,-100) 5(100,100)
  silkscreen extent -143,-143 191,466, body extent -136,-137 140,457, height 372
CP_8_2_ADI [mm]
  rect 0.808x0.255 smd paste+0 mask+0.051: 1(-1.522,0.75) 2(-1.522,0.25) 3(-1.522,-0.25) 4(-1.522,-0.75) 5(1.522,-0.75) 6(1.522,-0.25) 7(1.522,0.25) 8(1.522,0.75)
  rect 1.6x1.88 smd paste+0 mask+0.051: 9(0,0)
  silkscreen extent -1.75,-1.75 1.75,1.75, body extent -1.63,-1.63 1.63,1.63, height 0.84
CP_56_1_ADI [mm]
  rect 0.808x0.255 smd paste+0 mask+0.051: 1(-3.896,3.25) 2(-3.896,2.75) 3(-3.896,2.25) 4(-3.896,1.75) 5(-3.896,1.25) 6(-3.896,0.75) 7(-3.896,0.25) 8(-3.896,-0.25) 9(-3.896,-0.75) 10(-3.896,-1.25) 11(-3.896,-1.75) 12(-3.896,-2.25) 13(-3.896,-2.75) 14(-3.896,-3.25) 29(3.896,-3.25) 30(3.896,-2.75) 31(3.896,-2.25) 32(3.896,-1.75) 33(3.896,-1.25) 34(3.896,-0.75) 35(3.896,-0.25) 36(3.896,0.25) 37(3.896,0.75) 38(3.896,1.25) 39(3.896,1.75) 40(3.896,2.25) 41(3.896,2.75) 42(3.896,3.25)
  rect 0.255x0.808 smd paste+0 mask+0.051: 15(-3.25,-3.896) 16(-2.75,-3.896) 17(-2.25,-3.896) 18(-1.75,-3.896) 19(-1.25,-3.896) 20(-0.75,-3.896) 21(-0.25,-3.896) 22(0.25,-3.896) 23(0.75,-3.896) 24(1.25,-3.896) 25(1.75,-3.896) 26(2.25,-3.896) 27(2.75,-3.896) 28(3.25,-3.896) 43(3.25,3.896) 44(2.75,3.896) 45(2.25,3.896) 46(1.75,3.896) 47(1.25,3.896) 48(0.75,3.896) 49(0.25,3.896) 50(-0.25,3.896) 51(-0.75,3.896) 52(-1.25,3.896) 53(-1.75,3.896) 54(-2.25,3.896) 55(-2.75,3.896) 56(-3.25,3.896)
  rect 6.248x6.248 smd paste-3.111 mask+0.051: 57(0,0)
  silkscreen extent -4.13,-4.13 4.13,4.13, body extent -4,-4 4,4, height 0.99
FB0603 [mm]
  rect 0.7x0.9 smd mask+0.051: 1(-0.7,0) 2(0.7,0)
  silkscreen extent -1.2,-0.6 1.2,0.6, body extent -0.76,-0.38 0.76,0.38, height 0.8
FIDUCIAL [mil]
  round 40 smd mask+20: 1(0,0)
  TOP_L1 pour cut-out: 43.31,0 43.31,4.27 41.64,12.63 38.38,20.51 33.64,27.61 27.61,33.64 20.51,38.38 12.63,41.64 4.27,43.31 0,43.31 -4.27,43.31 -12.63,41.64 -20.51,38.38 -27.61,33.64 -33.64,27.61 -38.38,20.51 -41.64,12.63 -43.31,4.27 -43.31,0 -43.31,-4.27 -41.64,-12.63 -38.38,-20.51 -33.64,-27.61 -27.61,-33.64 -20.51,-38.38 -12.63,-41.64 -4.27,-43.31 0,-43.31 4.27,-43.31 12.63,-41.64 20.51,-38.38 27.61,-33.64 33.64,-27.61 38.38,-20.51 41.64,-12.63 43.31,-4.27 43.31,0
HEADER_10X2 [mm]
  rect 1.7x1.7 hole 1.1 mask+0.05: 1(0,0)
  round 1.7 hole 1.1 mask+0.05: 2(0,2.54) 3(2.54,0) 4(2.54,2.54) 5(5.08,0) 6(5.08,2.54) 7(7.62,0) 8(7.62,2.54) 9(10.16,0) 10(10.16,2.54) 11(12.7,0) 12(12.7,2.54) 13(15.24,0) 14(15.24,2.54) 15(17.78,0) 16(17.78,2.54) 17(20.32,0) 18(20.32,2.54) 19(22.86,0) 20(22.86,2.54)
  silkscreen extent -1.27,-1.17 24.13,3.71, body extent -1.27,-1.27 24.13,3.81, height 7.75
"HOLE 3MM" [mm] "hole 3mm"
  round 4 hole 3.2: 1(0,0)
IND6X6_H3 [mm]
  rect 2.3x6.6 smd mask+0.051: 1(-2.15,0) 2(2.15,0)
  silkscreen extent -3.5,-3.56 3.5,3.5, body extent -3.1,-3.1 3.1,3.1, height 3.5
LED_0603_GREEN [mm] "LED 0603, Green"
  rect 0.7x0.9 smd mask+0.051: 1(-0.7,0) 2(0.7,0)
  silkscreen extent -1.14,-0.6 1.52,0.6, body extent -0.8,-0.4 0.8,0.4, height 0.7
MICTOR-38_PIN [mm]
  round 1.524 hole 2.43: 0(5.71,-3.495)
  rrect50% 0.43x1.6 smd mask+0.051: 1(0,0) 2(0,-6.99) 3(-0.635,0) 4(-0.635,-6.99) 5(-1.27,0) 6(-1.27,-6.99) 7(-1.905,0) 8(-1.905,-6.99) 9(-2.54,0) 10(-2.54,-6.99) 11(-3.175,0) 12(-3.175,-6.99) 13(-3.81,0) 14(-3.81,-6.99) 15(-4.445,0) 16(-4.445,-6.99) 17(-5.08,0) 18(-5.08,-6.99) 19(-5.715,0) 20(-5.715,-6.99) 21(-6.35,0) 22(-6.35,-6.99) 23(-6.985,0) 24(-6.985,-6.99) 25(-7.62,0) 26(-7.62,-6.99) 27(-8.255,0) 28(-8.255,-6.99) 29(-8.89,0) 30(-8.89,-6.99) 31(-9.525,0) 32(-9.525,-6.99) 33(-10.16,0) 34(-10.16,-6.99) 35(-10.795,0) 36(-10.795,-6.99) 37(-11.43,0) 38(-11.43,-6.99)
  round 1.2 hole 0.86: 39(-0.64,-3.495) 40(-3.18,-3.495) 41(-5.72,-3.495) 42(-8.26,-3.495) 43(-10.8,-3.495)
  silkscreen extent -18.8,-6.99 7.3,0, body extent -18.42,-7.85 6.98,0.86, height 6.05
NXP_74AVC4T245GU,115 [mm]
  rect 0.65x0.22 smd mask+0.051: 1(-0.725,0.6)
  rect 0.55x0.22 smd mask+0.051: 2(-0.775,0.2) 3(-0.775,-0.2) 4(-0.775,-0.6) 9(0.775,-0.6) 10(0.775,-0.2) 11(0.775,0.2) 12(0.775,0.6)
  rect 0.22x0.55 smd mask+0.051: 5(-0.6,-1.175) 6(-0.2,-1.175) 7(0.2,-1.175) 8(0.6,-1.175) 13(0.6,1.175) 14(0.2,1.175) 15(-0.2,1.175) 16(-0.6,1.175)
  silkscreen extent -1.05,-1.45 1.05,1.45, body extent -0.9,-1.3 0.9,1.3, height 0.5
PCIE_8LANE_EDGE [mil] "PCIE_8LANE_EDGE"
  rect 28x126 smd far side paste-100: A1(-984.25,-93.98)
  rect 28x169 smd far side paste-100: A2(-944.88,-115.48) A3(-905.51,-115.48) A4(-866.14,-115.48) A5(-826.77,-115.48) A6(-787.4,-115.48) A7(-748.03,-115.48) A8(-708.66,-115.48) A9(-669.29,-115.48) A10(-629.92,-115.48) A11(-590.55,-115.48) A12(-472.44,-115.48) A13(-433.07,-115.48) A14(-393.7,-115.48) A15(-354.33,-115.48) A16(-314.96,-115.48) A17(-275.59,-115.48) A18(-236.22,-115.48) A19(-196.85,-115.48) A20(-157.48,-115.48) A21(-118.11,-115.48) A22(-78.74,-115.48) A23(-39.37,-115.48) A24(0,-115.48) A25(39.37,-115.48) A26(78.74,-115.48) A27(118.11,-115.48) A28(157.48,-115.48) A29(196.85,-115.48) A30(236.22,-115.48) A31(275.59,-115.48) A32(314.96,-115.48)
  rect 28x169 smd paste-100 mask+2: B1(-984.25,-115.48) B2(-944.88,-115.48) B3(-905.51,-115.48) B4(-866.14,-115.48) B5(-826.77,-115.48) B6(-787.4,-115.48) B7(-748.03,-115.48) B8(-708.66,-115.48) B9(-669.29,-115.48) B10(-629.92,-115.48) B11(-590.55,-115.48) B12(-472.44,-115.48) B13(-433.07,-115.48) B14(-393.7,-115.48) B15(-354.33,-115.48) B16(-314.96,-115.48) B18(-236.22,-115.48) B19(-196.85,-115.48) B20(-157.48,-115.48) B21(-118.11,-115.48) B22(-78.74,-115.48) B23(-39.37,-115.48) B24(0,-115.48) B25(39.37,-115.48) B26(78.74,-115.48) B27(118.11,-115.48) B28(157.48,-115.48) B29(196.85,-115.48) B30(236.22,-115.48) B32(314.96,-115.48)
  rect 28x126 smd paste-100 mask+2: B17(-275.59,-93.98) B31(275.59,-93.98)
R0402 [mil] "R0402"
  rect 25x25 smd mask+2: 1(-18.5,0) 2(20.9,0)
  silkscreen extent -36,-17 40,17, body extent -20,-10 20,10, height 14
r0402 [mil] "R0402"
  rect 25x25 smd mask+2: 1(-18.5,0) 2(20.9,0)
  silkscreen extent -36,-17 40,17, body extent -20,-10 20,10, height 14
